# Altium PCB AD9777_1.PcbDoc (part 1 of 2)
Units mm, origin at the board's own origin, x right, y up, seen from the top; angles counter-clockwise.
Board outline 148.59 x 134.62 mm, 4 copper layers (Top Layer, Ground, POwer, Bottom Layer), stack 0.778 mm thick; 277 components, 168 nets, 827 pads, 113 vias.
Unrouted connection lines stored in the file: 4.
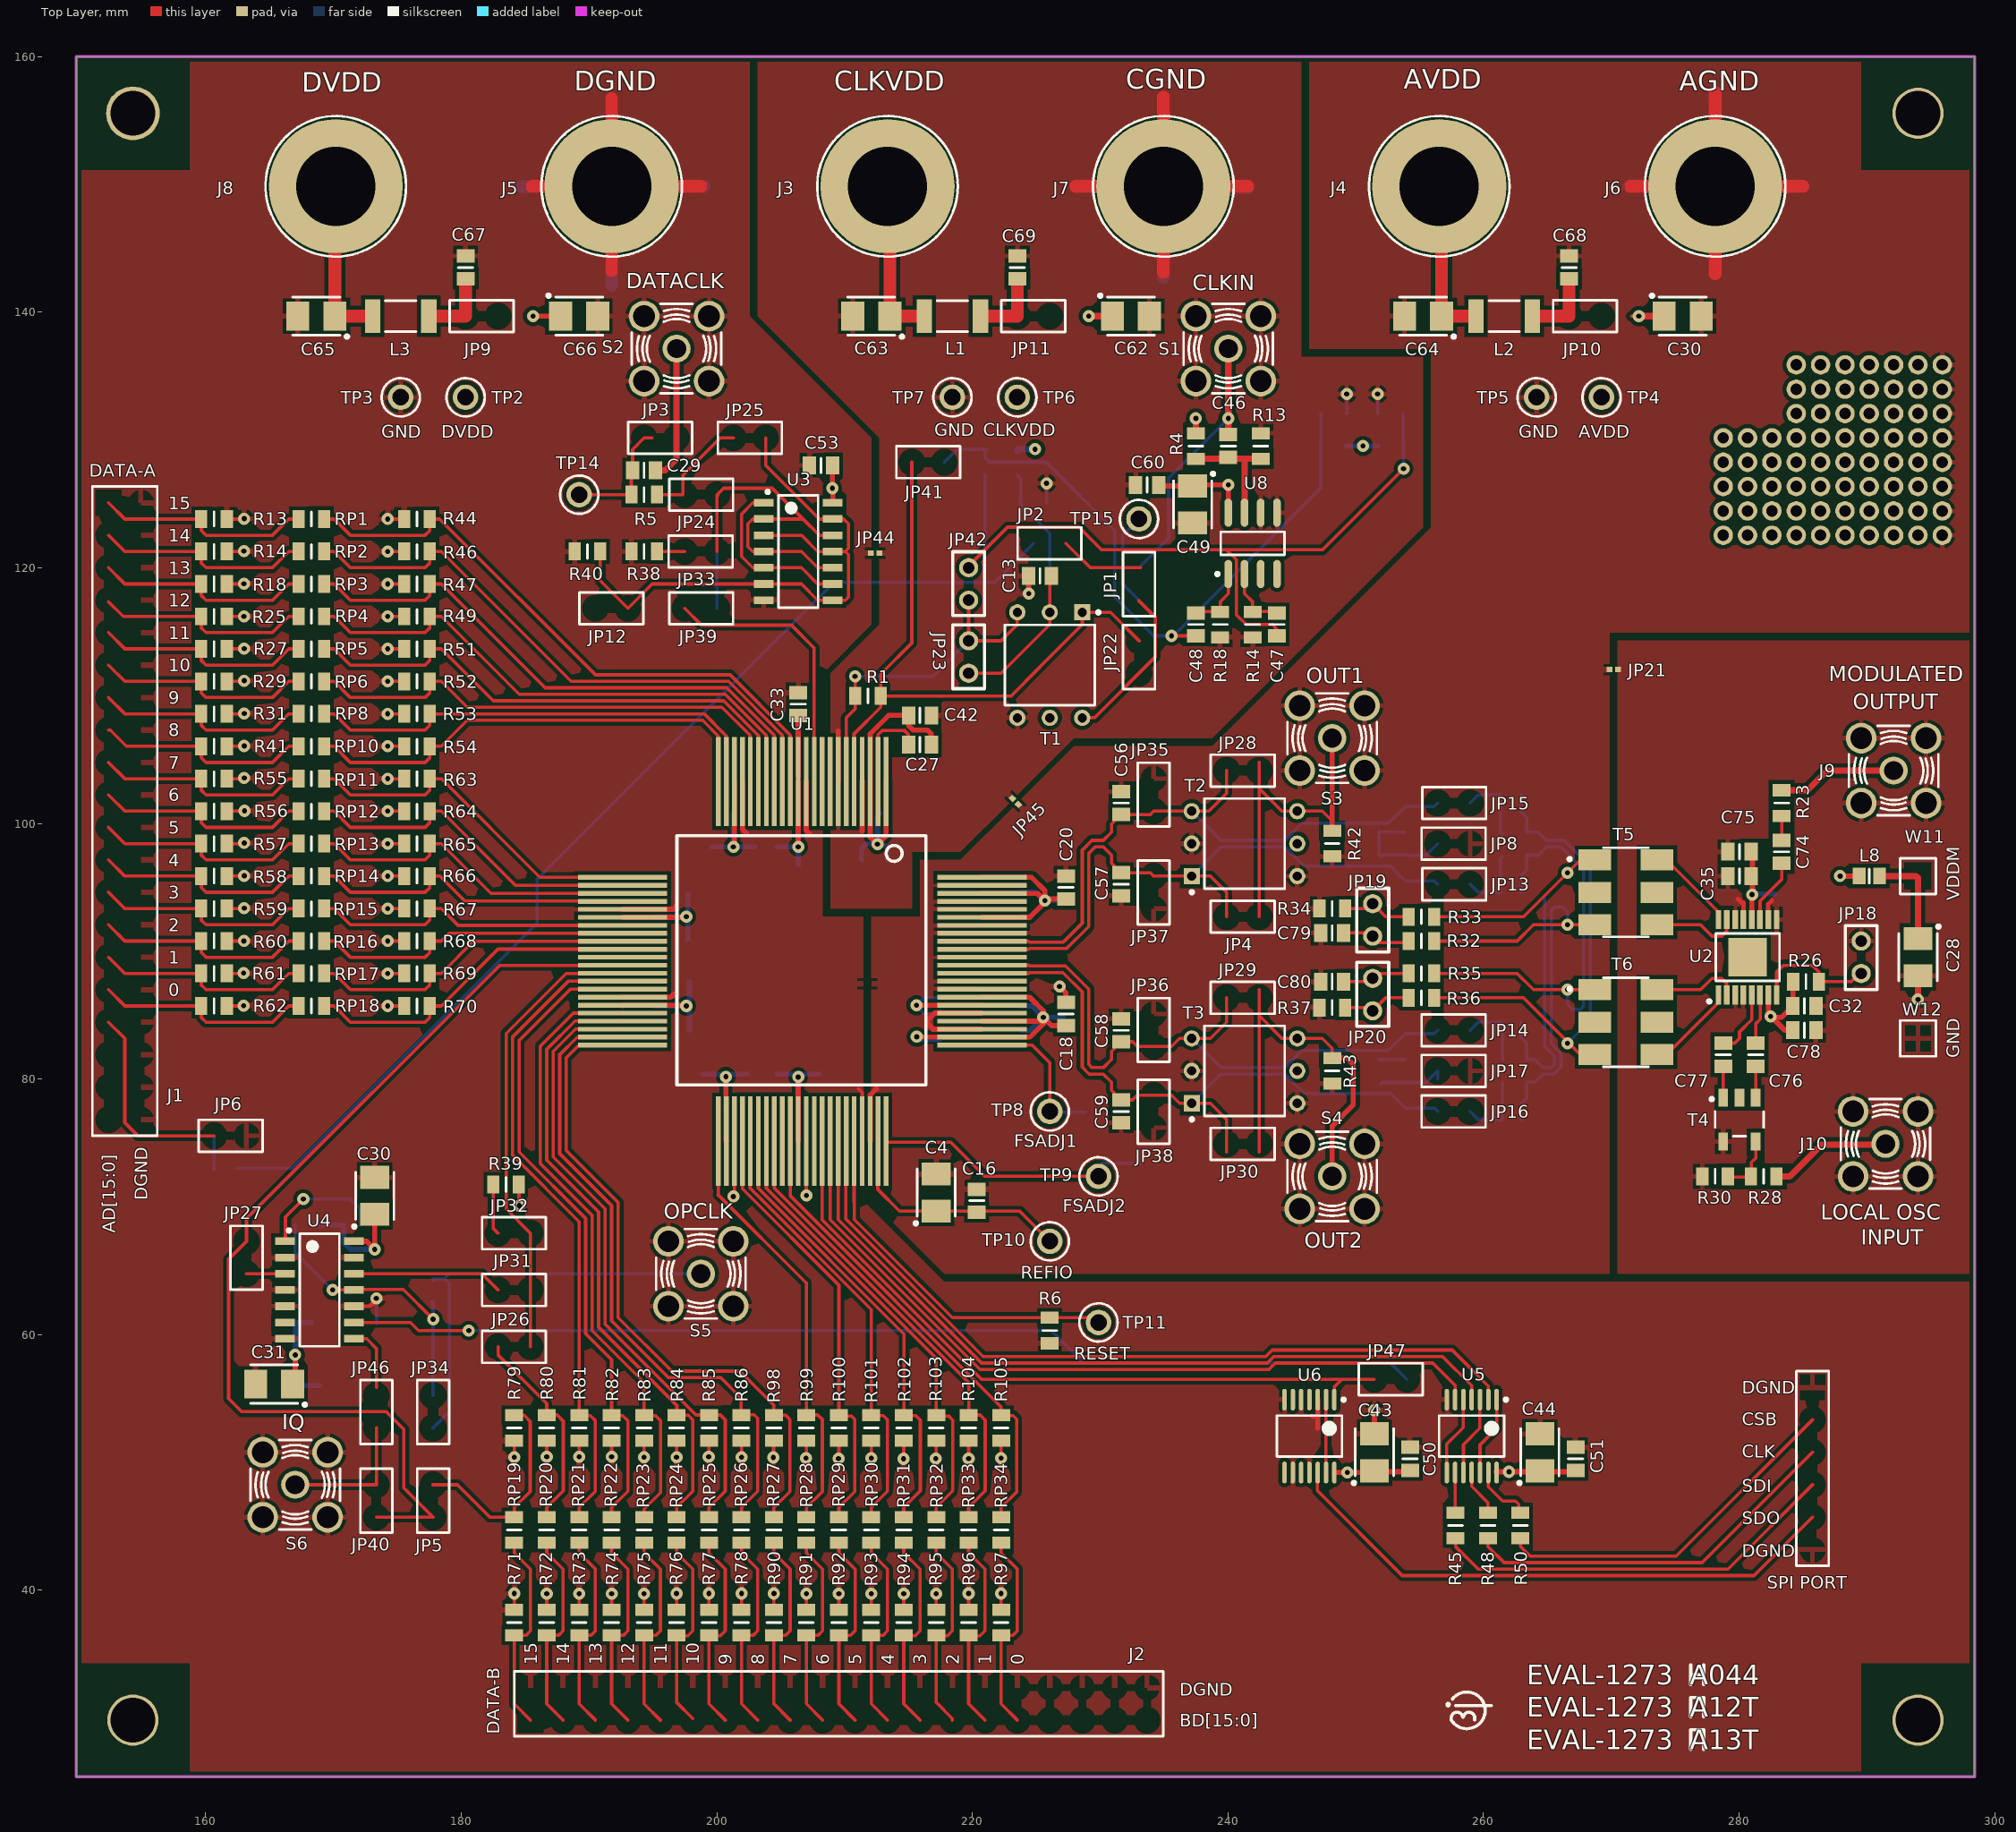
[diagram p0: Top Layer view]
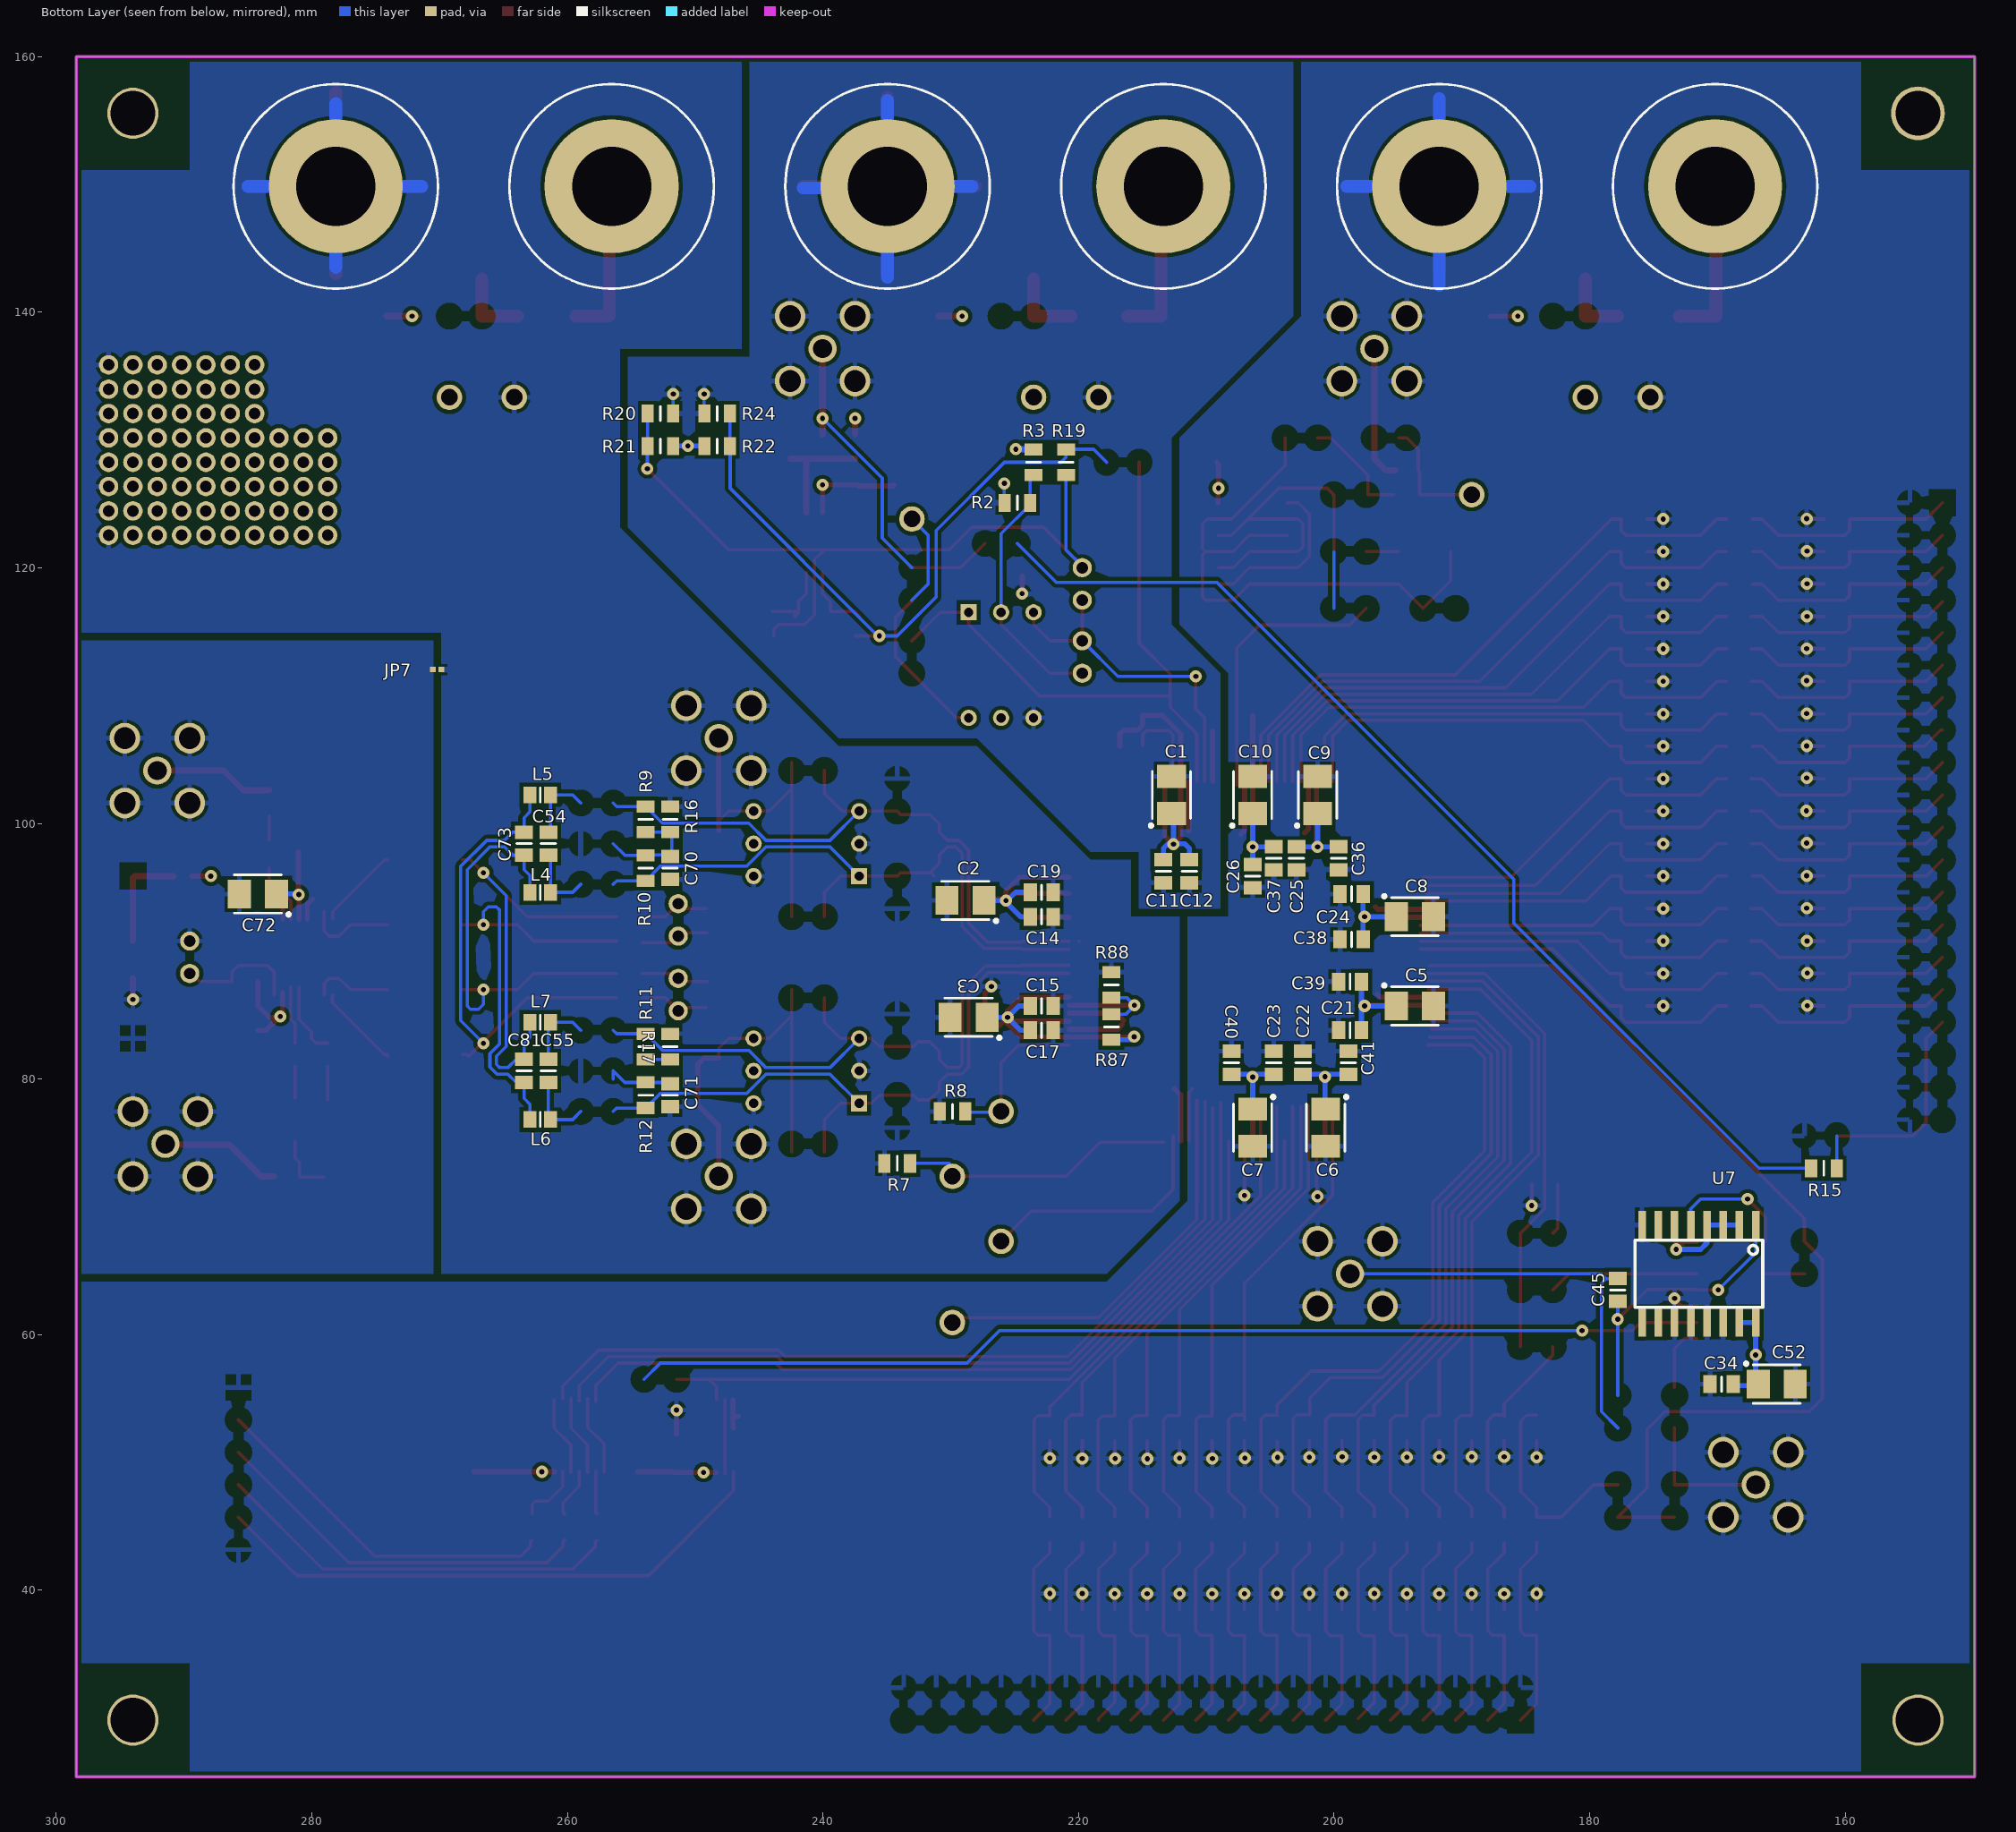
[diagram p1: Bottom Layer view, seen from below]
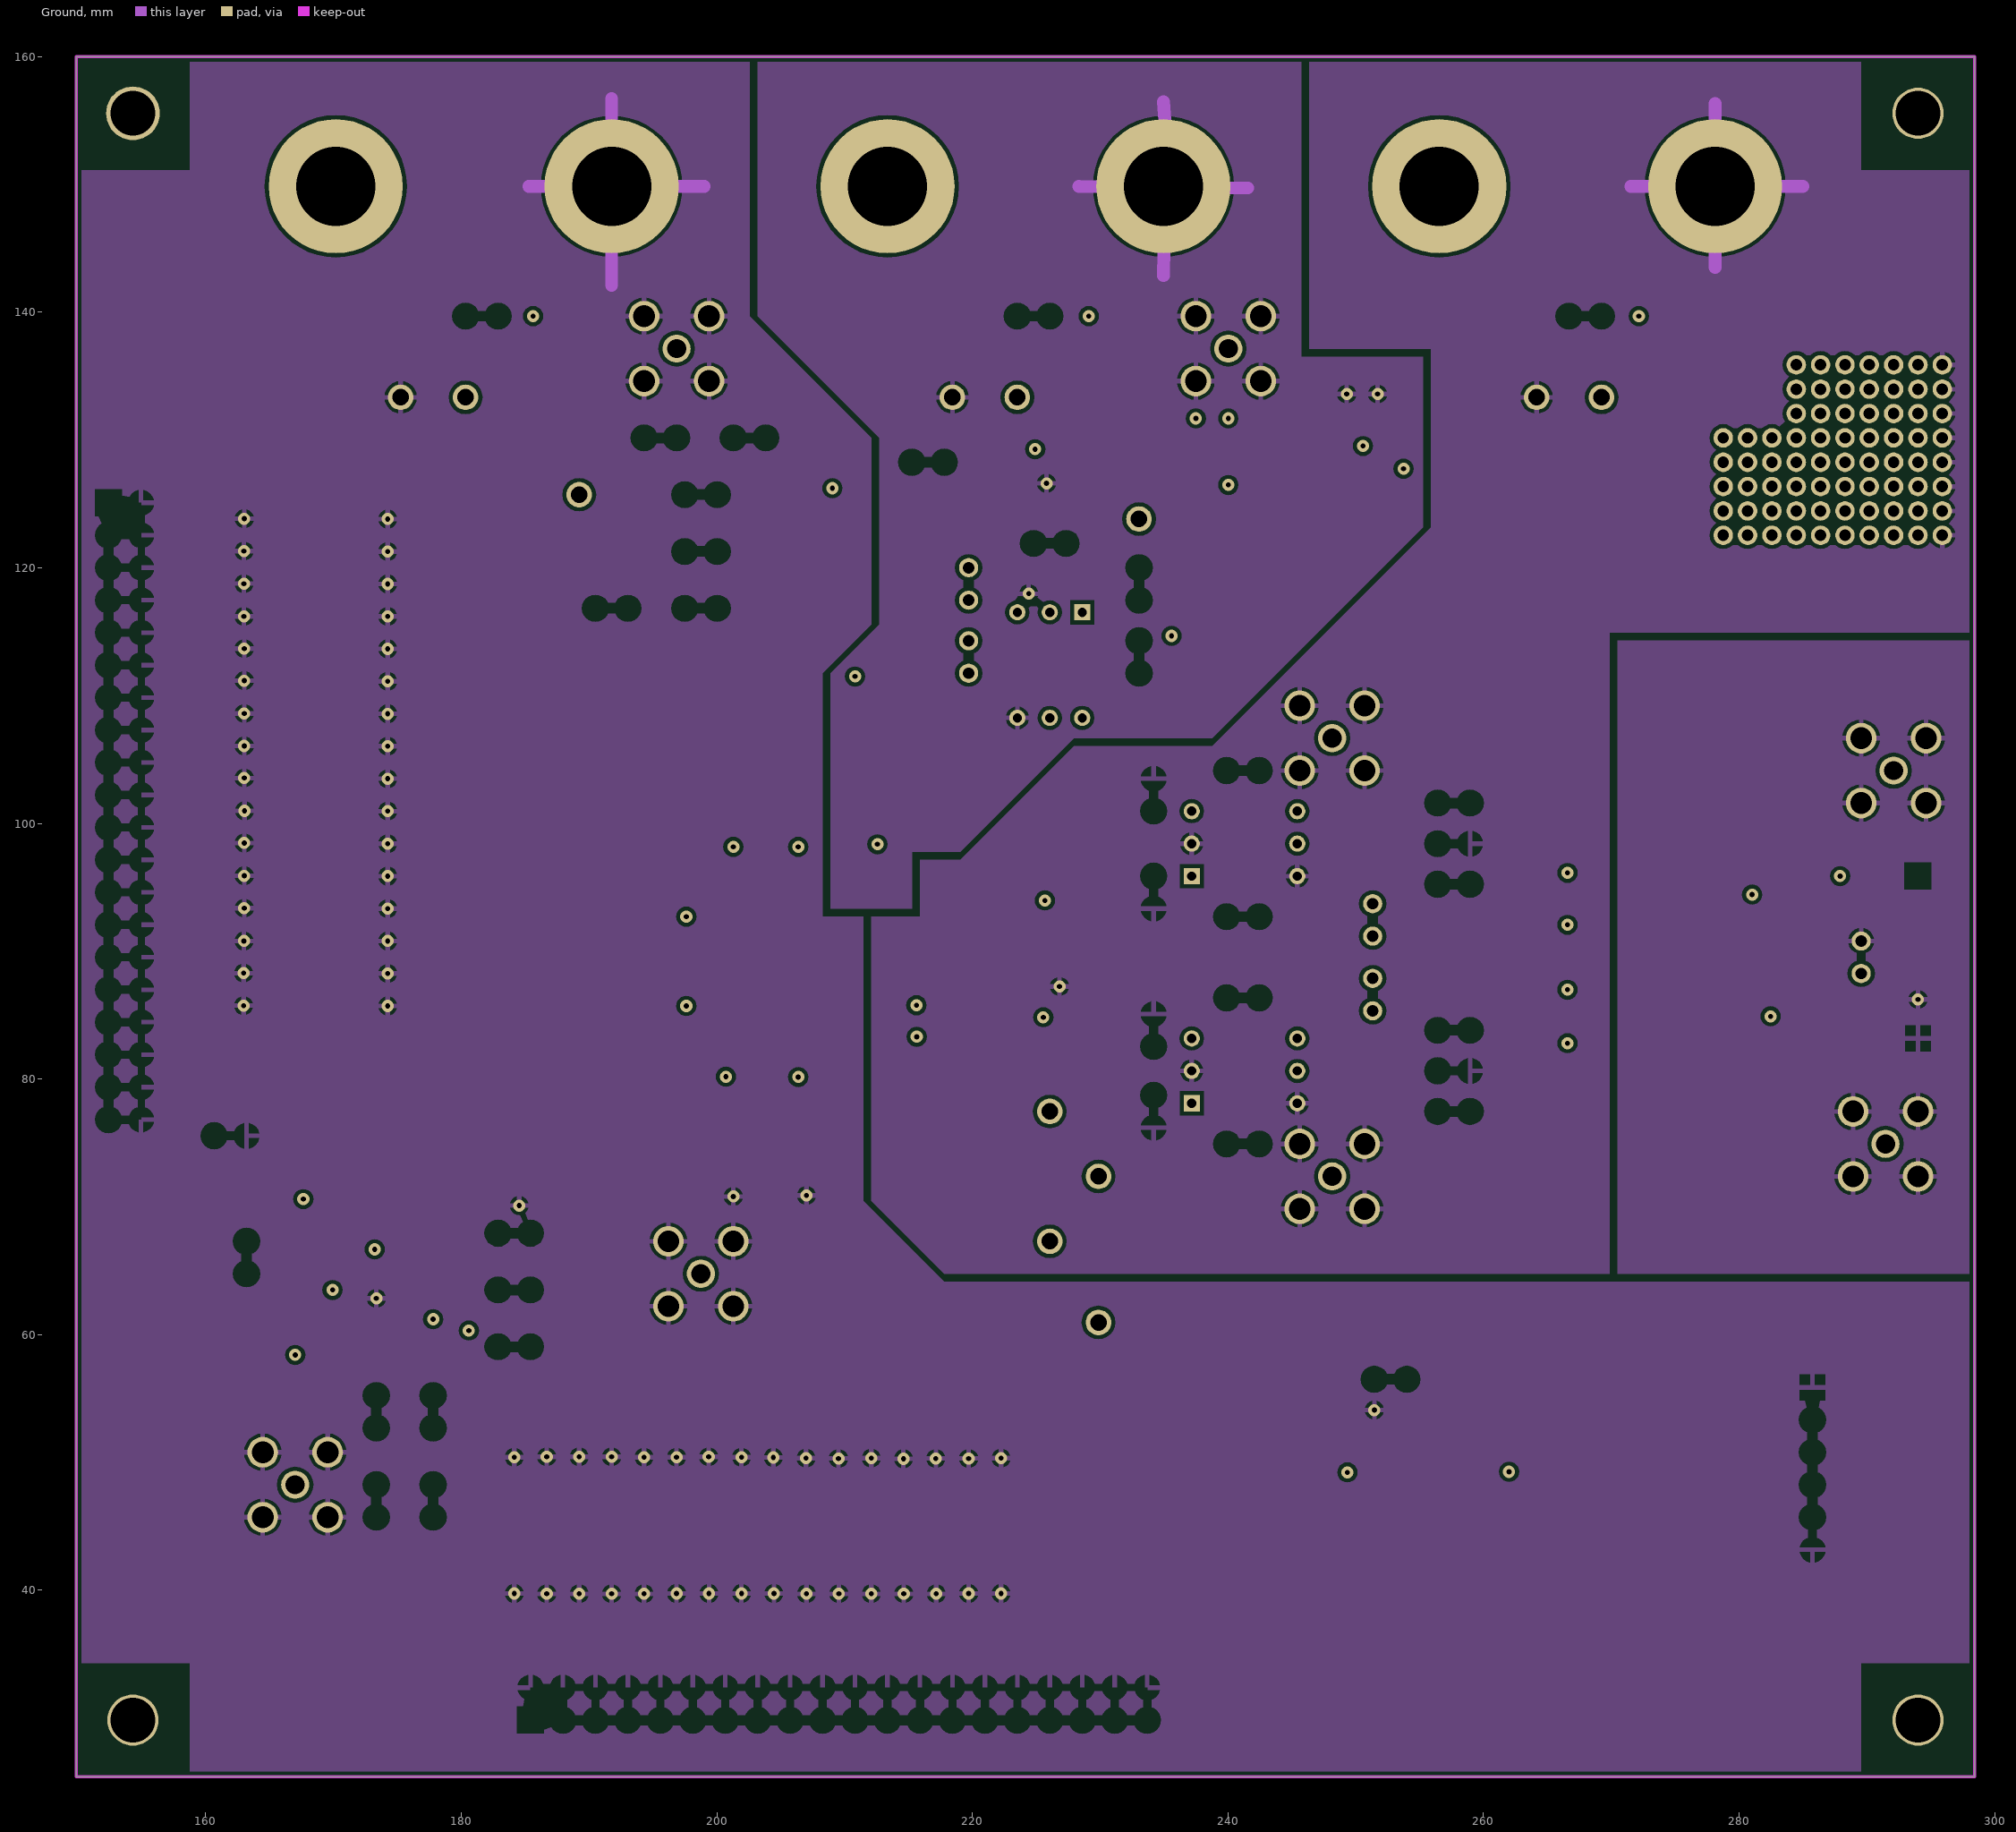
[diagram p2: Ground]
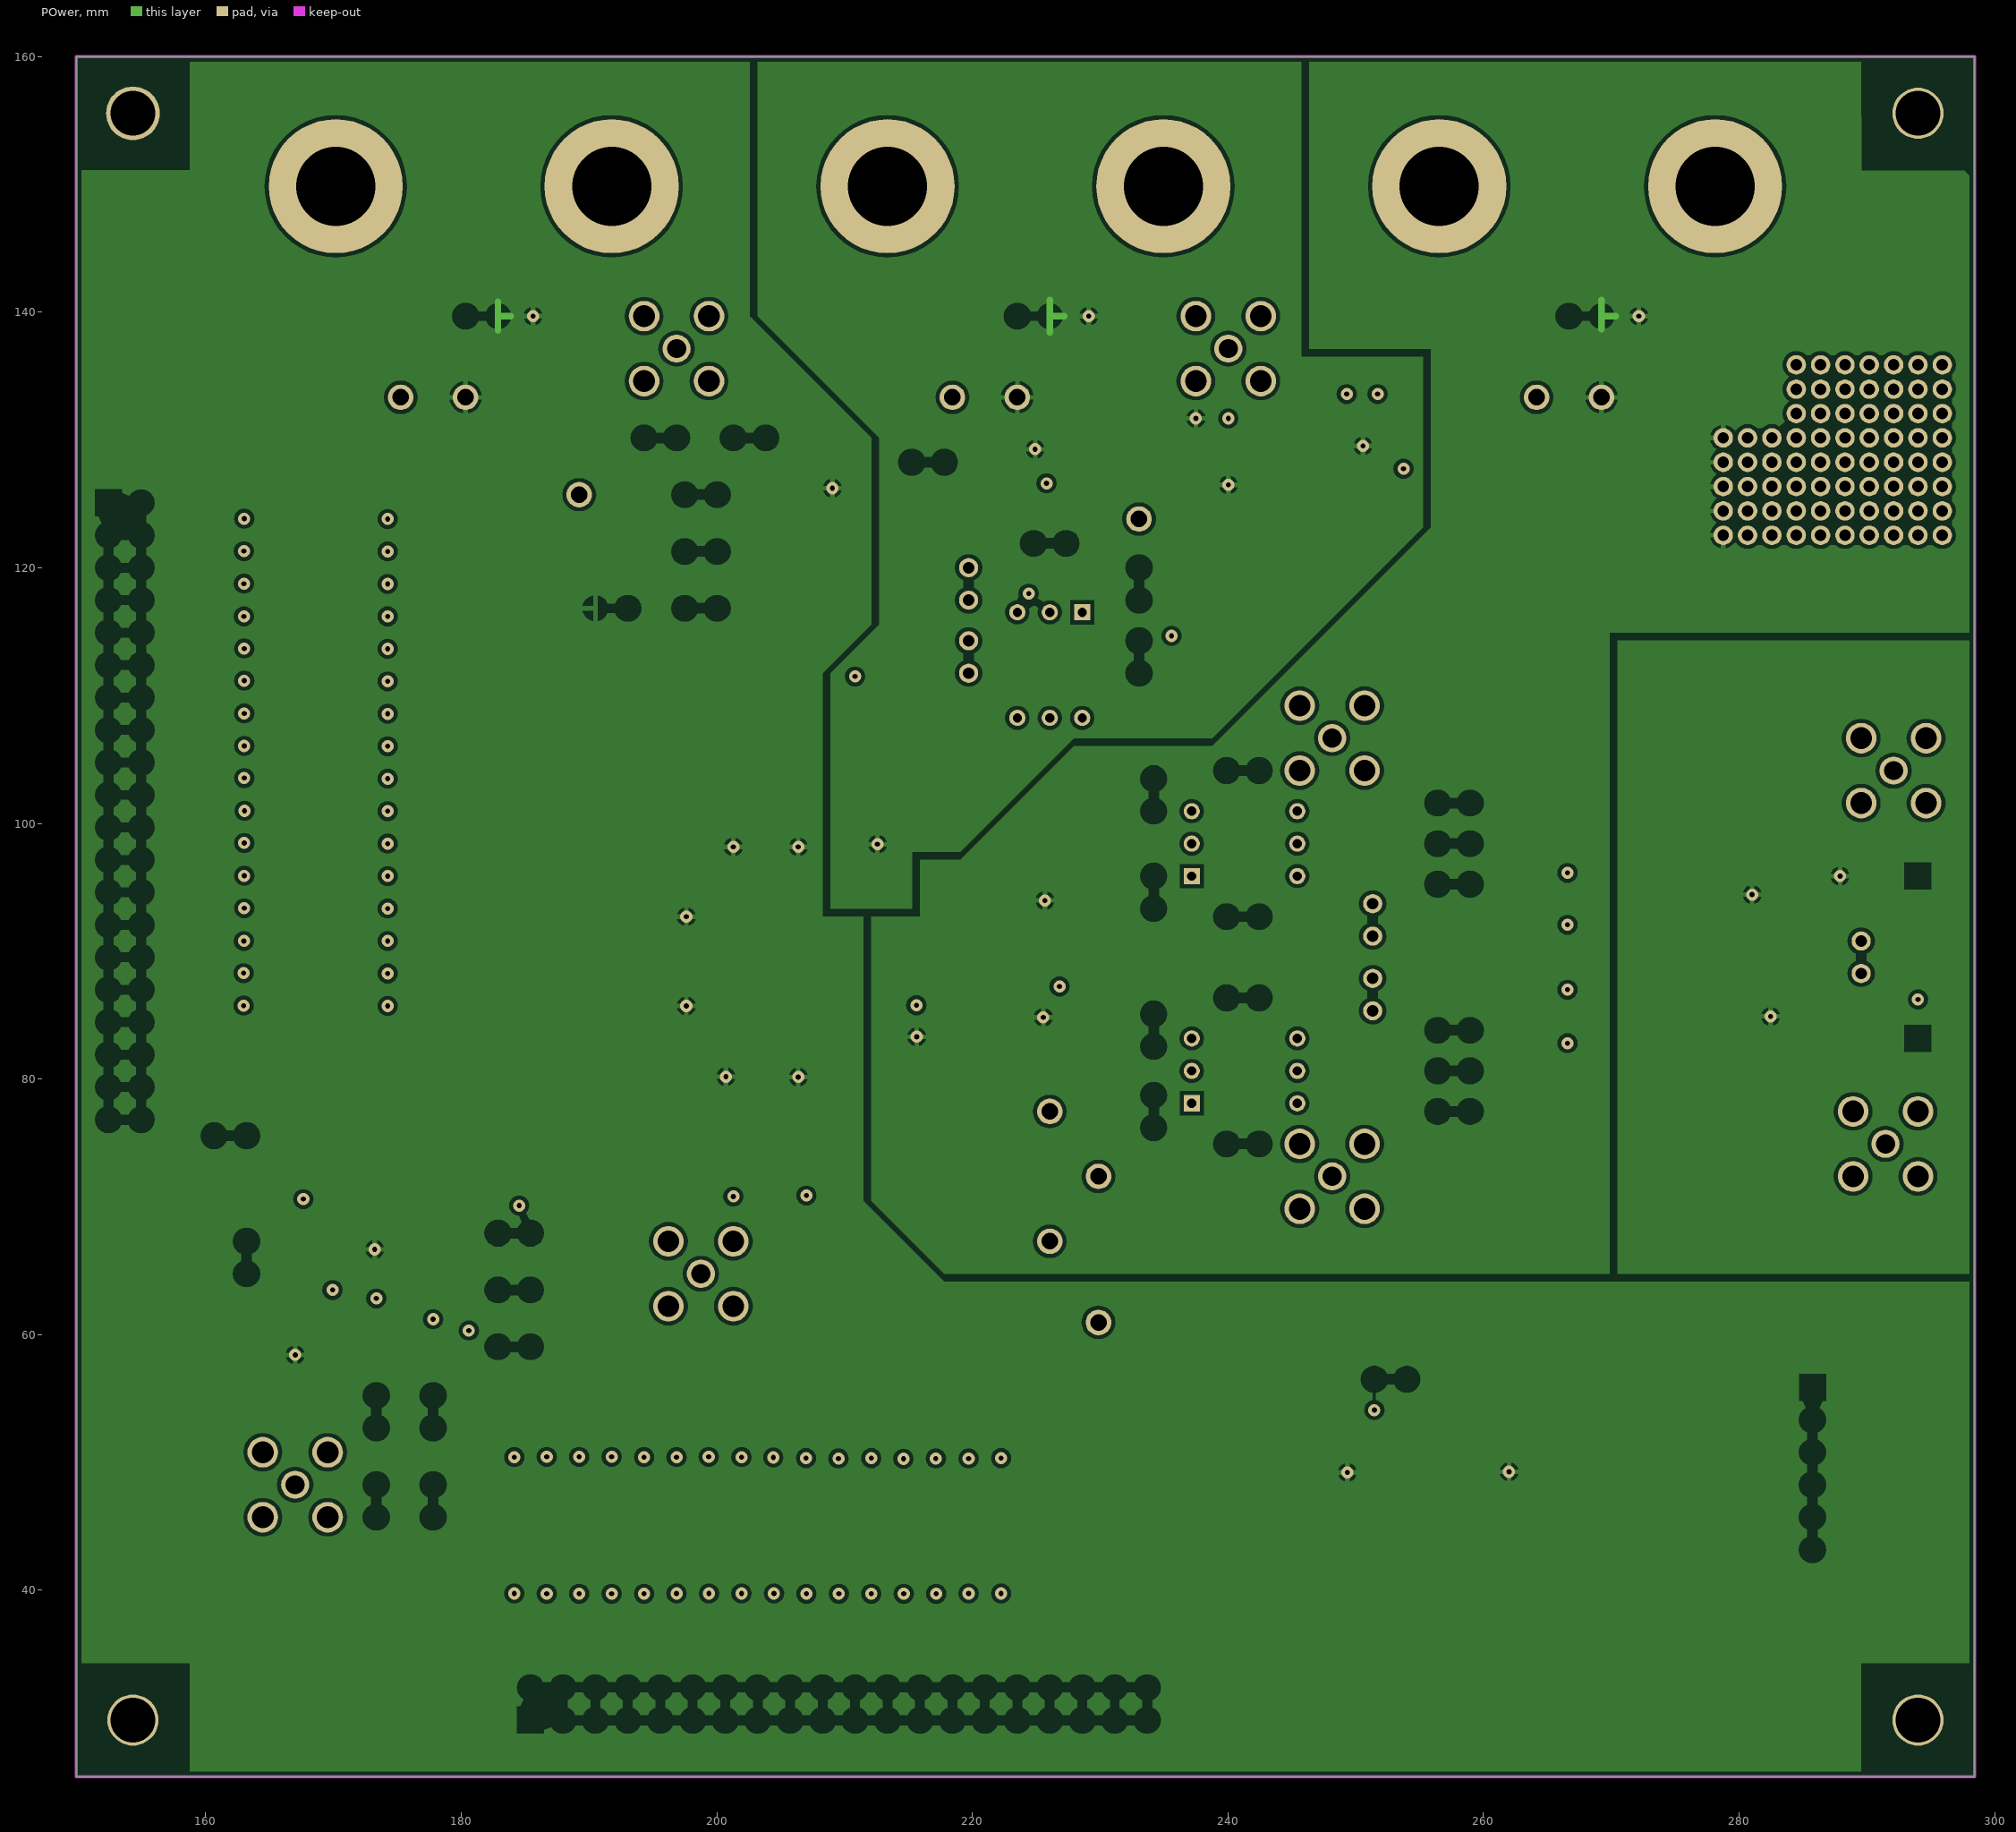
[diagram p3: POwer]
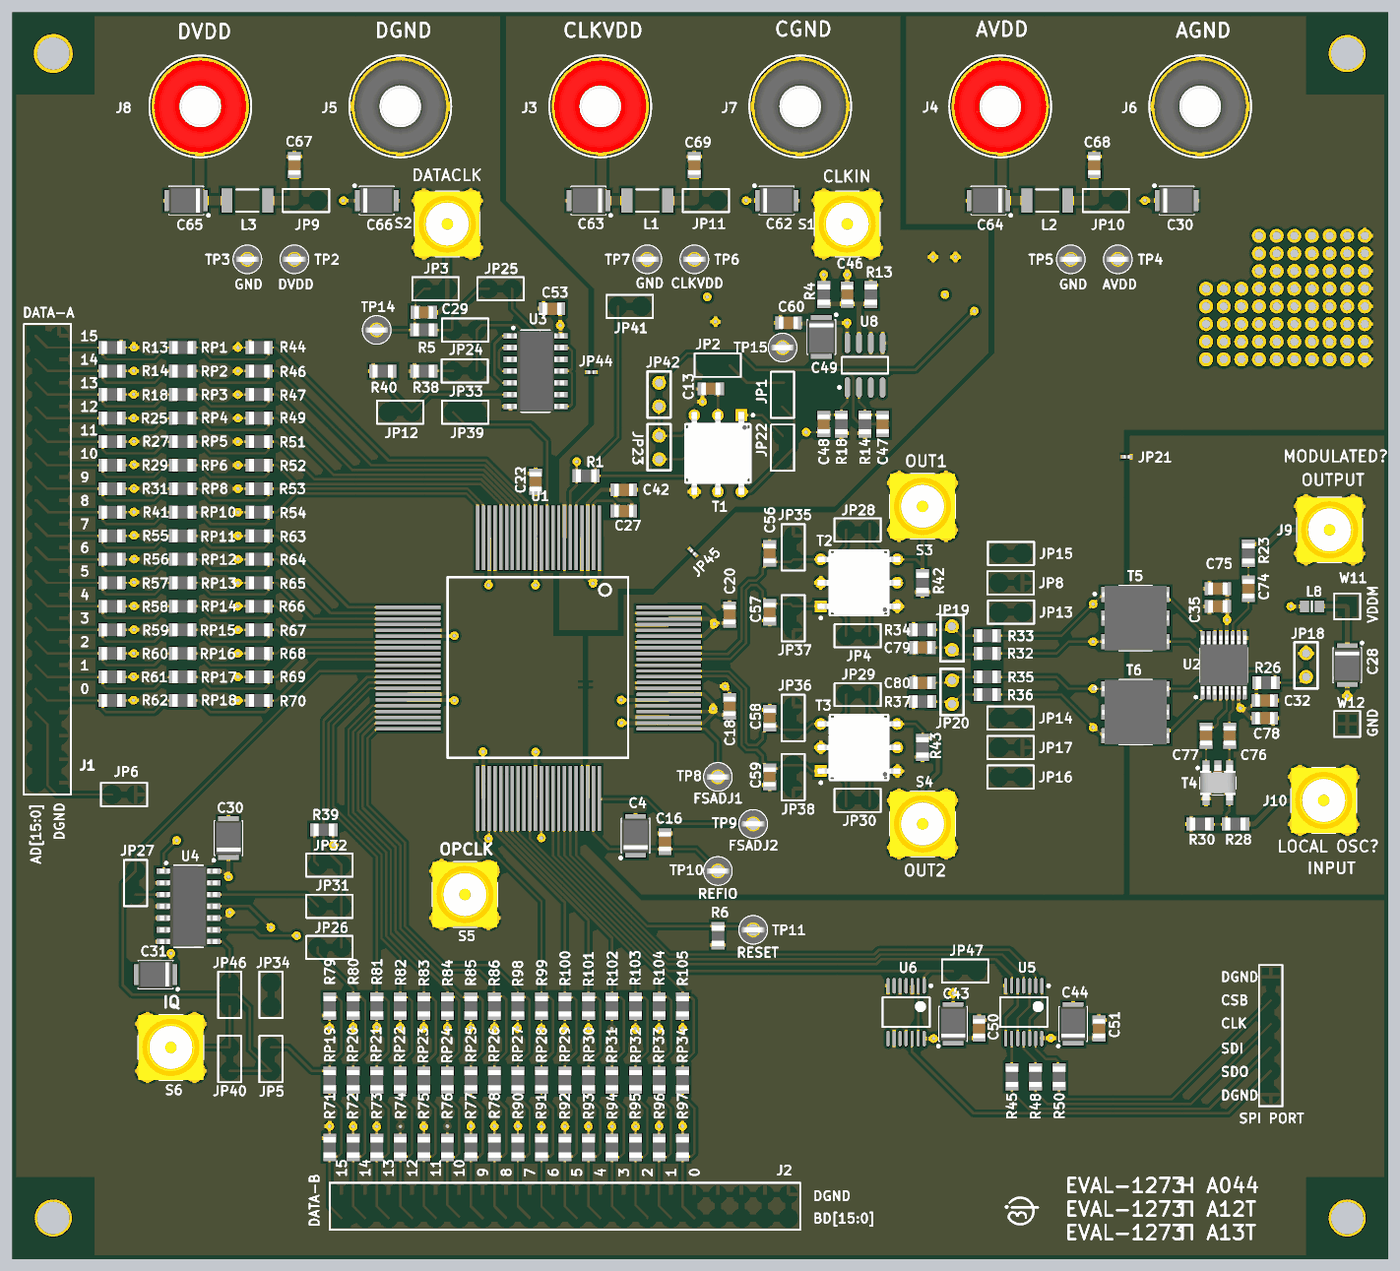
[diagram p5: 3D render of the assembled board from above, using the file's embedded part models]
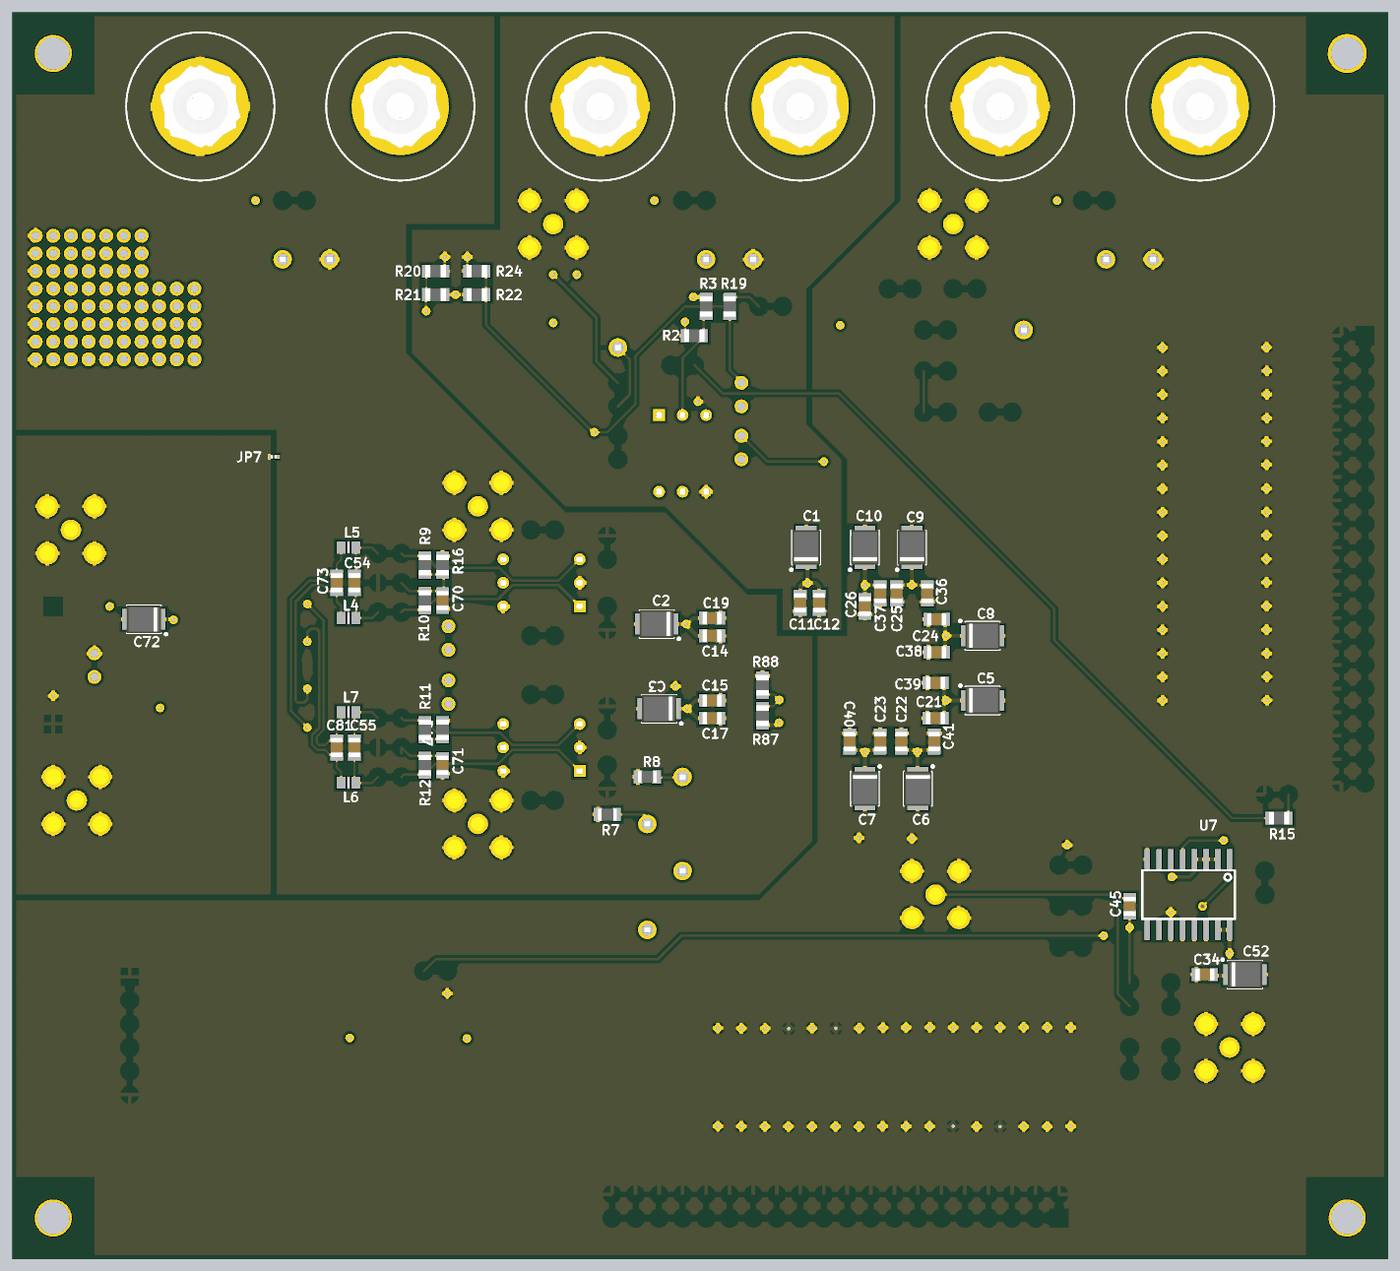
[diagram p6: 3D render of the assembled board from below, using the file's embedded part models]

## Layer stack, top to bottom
Top Solder: solder mask 0.0102, Solder Resist, Dk 3.5
Top Layer: signal copper 0.0356
Dielectric1: core 0.254, FR-4, Dk 4.2
Ground: signal copper 0.036
Dielectric2: prepreg 0.127, Dk 4.2
POwer: signal copper 0.036
Dielectric3: core 0.254, Dk 4.2
Bottom Layer: signal copper 0.0356
Bottom Solder: solder mask 0.0102, Solder Resist, Dk 3.5

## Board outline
149.86,160.02 298.45,160.02 298.45,25.4 149.86,25.4

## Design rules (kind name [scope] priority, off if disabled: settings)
Clearance Clearance_1 [All vs InPolygon] p1: gap=0.3 ignorepadtopadclearanceinfootprint=FALSE except(0: Arc-Hole Track-Hole SMDPad-Hole THPad-Hole Via-Hole Fill-Hole Poly-Hole Region-Hole Text-Hole) // Polygon
Clearance [All] p2: gap=0.1 ignorepadtopadclearanceinfootprint=FALSE except(0: Arc-Hole Track-Hole SMDPad-Hole THPad-Hole Via-Hole Fill-Hole Poly-Hole Region-Hole Text-Hole)
DiffPairsRouting DiffPairsRouting_1 [All] p1: maxlimit=0.254 minlimit=0.2 mostfreqgap=0.254 toplayer_minwidth=0.381 toplayer_maxwidth=0.381 toplayer_prefwidth=0.381 midlayer1_minwidth=0.381 midlayer1_maxwidth=0.381 midlayer1_prefwidth=0.381 midlayer2_minwidth=0.381 midlayer2_maxwidth=0.381 midlayer2_prefwidth=0.381 bottomlayer_minwidth=0.381 bottomlayer_maxwidth=0.381 bottomlayer_prefwidth=0.381 maxuncoupledlength=20
DiffPairsRouting [All] p2: maxlimit=0.254 minlimit=0.1 mostfreqgap=0.254 toplayer_minwidth=0.381 toplayer_maxwidth=0.381 toplayer_prefwidth=0.381 midlayer1_minwidth=0.381 midlayer1_maxwidth=0.381 midlayer1_prefwidth=0.381 midlayer2_minwidth=0.381 midlayer2_maxwidth=0.381 midlayer2_prefwidth=0.381 bottomlayer_minwidth=0.381 bottomlayer_maxwidth=0.381 bottomlayer_prefwidth=0.381 maxuncoupledlength=20
MatchedLengths [All] p1: tolerance=2.4 checknetsindiffpair=TRUE checkdiffpairvsdiffpair=FALSE checkxsignals=FALSE checkothers=FALSE
ParallelSegment [All] p1: limit=254 gap=0.254
PolygonConnect [All] p1: connectstyle=Relief reliefconductorwidth=0.4 reliefentries=4 polygonreliefangle="90 Angle" airgapwidth=0.254
RoutingVias [All] p1: holewidth=0.711 width=1.27 viastyle="Through Hole" minholewidth=0.711 minwidth=1.27 maxholewidth=0.711 maxwidth=1.27
SolderMaskExpansion [All] p1: expansion=0.102
Width Width_1 [All] p1: maxlimit=1 minlimit=0.1 preferedwidth=0.254
Width [All] p2: maxlimit=1 minlimit=0.1 preferedwidth=0.254
29 further rules are at their usual default settings.

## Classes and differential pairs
component class AD9777_L1: C28 C30 C32 C35 C54 C55 C62 C63 C64 C65 C66 C67 C68 C69 C72 C73 C74 C75 C76 C77 C78 C79 C80 C81 J3 J4 J5 J6 J7 J8 J9 J10 JP7 JP18 JP19 JP20 JP21 JP44 JP45 L1 L2 L3 L4 L5 L6 L7 L8 R23 R26 R28 R30 R32 R33 R34 R35 R36 R37 T4 T5 T6 TP2 TP3 TP4 TP5 TP6 TP7 U2 W11 W12
component class AD9777_L2: C1 C2 C3 C4 C5 C6 C7 C8 C9 C10 C11 C12 C13 C14 C15 C16 C17 C18 C19 C20 C21 C22 C23 C24 C25 C26 C27 C29 C36 C37 C38 C39 C40 C41 C42 C45 C56 C57 C58 C59 C70 C71 JP23 R1 R2 R3 R5 R6 R7 R8 R9 R10 R11 R12 R16 R17 R38 R39 R40 R42 R43 R87 R88 S1 S2 S3 S4 S5 S6 T1 T2 T3 TP8 TP9 TP10 TP11 TP14 TP15 TR3 U1
component class AD9777_L3: C30 C31 C33 C34 C52 C53 R13 R14 R15 R18 R25 R27 R29 R31 R41 R44 R46 R47 R49 R51 R52 R53 R54 R55 R56 R57 R58 R59 R60 R61 R62 R63 R64 R65 R66 R67 R68 R69 R70 RP1 RP2 RP3 RP4 RP5 RP6 RP8 RP10 RP11 RP12 RP13 RP14 RP15 RP16 RP17 RP18 U3 U4 U7
component class AD9777_L4: C43 C44 C46 C47 C48 C49 C50 C51 C60 JP42 R4 R13 R14 R18 R19 R20 R21 R22 R24 R45 R48 R50 R71 R72 R73 R74 R75 R76 R77 R78 R79 R80 R81 R82 R83 R84 R85 R86 R90 R91 R92 R93 R94 R95 R96 R97 R98 R99 R100 R101 R102 R103 R104 R105 RP19 RP20 RP21 RP22 RP23 RP24 RP25 RP26 RP27 RP28 RP29 RP30 RP31 RP32 RP33 RP34 U5 U6 U8
differential pair O1: +O1_P -O1_N
differential pair O2: +O2_P -O2_N
differential pair IOUTA1: +IOUTA1_P -IOUTA1_N
differential pair IOUTA2: +IOUTA2_P -IOUTA2_N
differential pair IBB: +IBB_P -IBB_N
differential pair LOI: +LOI_P -LOI_N
differential pair QBB: +QBB_P -QBB_N

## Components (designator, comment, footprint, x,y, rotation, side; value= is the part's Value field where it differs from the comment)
C1 "10uF" CAPMP3528X210N 212.725,102.235 r90 bottom
C2 "10uF" CAPMP3528X210N 228.854,93.98 r0 bottom
C3 "10uF" CAPMP3528X210N 228.6,84.836 r0 bottom
C4 "10uF" CAPMP3528X210N 217.17,71.12 r90 top
C5 "10uF" CAPMP3528X210N 193.675,85.725 r180 bottom
C6 "10uF" CAPMP3528X210N 200.66,76.2 r270 bottom
C7 "10uF" CAPMP3528X210N 206.375,76.2 r270 bottom
C8 "10uF" CAPMP3528X210N 193.675,92.71 r180 bottom
C9 "10uF" CAPMP3528X210N 201.295,102.235 r90 bottom
C10 "10uF" CAPMP3528X210N 206.375,102.235 r90 bottom
C11 "0.1uF" CAPC2012X135N 213.36,96.266 r270 bottom
C12 "0.1uF" CAPC2012X135N 211.328,96.266 r270 bottom
C13 "0.1uF" CAPC2012X135N 225.298,119.38 r0 top
C14 "0.1uF" CAPC2012X135N 222.885,92.71 r180 bottom
C15 "0.1uF" CAPC2012X135N 222.885,85.725 r180 bottom
C16 "0.1uF" CAPC2012X135N 220.345,70.485 r90 top
C17 "0.1uF" CAPC2012X135N 222.885,83.82 r180 bottom
C18 "0.1uF" CAPC2012X135N 227.33,85.09 r90 top
C19 "0.1uF" CAPC2012X135N 222.885,94.615 r180 bottom
C20 "0.1uF" CAPC2012X135N 227.33,94.996 r90 top
C21 "1nF" CAPC2012X135N 198.755,83.82 r0 bottom
C22 "1nF" CAPC2012X135N 202.438,81.28 r90 bottom
C23 "1nF" CAPC2012X135N 204.724,81.28 r90 bottom
C24 "1nF" CAPC2012X135N 198.628,94.488 r0 bottom
C25 "1nF" CAPC2012X135N 202.946,97.282 r270 bottom
C26 "1nF" CAPC2012X135N 206.375,95.885 r270 bottom
C27 "1pF" CAPC2012X135N 215.9,106.172 r180 top
C28 "22uF" CAPMP3528X210N 294.005,89.535 r270 top
C29 "0.1uF" CAPC2012X135N 194.31,127.635 r0 top
C30 "4.7uF" CAPMP3528X210N 173.228,70.866 r90 top
C30 "22uF" CAPMP3528X210N 275.59,139.7 r0 top
C31 "4.7uF" CAPMP3528X210N 165.354,56.134 r180 top
C32 "0.1uF" CAPC2012X135N 285.115,85.725 r0 top
C33 "0.1uF" CAPC2012X135N 206.375,109.347 r90 top
C34 "0.1uF" CAPC2012X135N 169.672,56.134 r0 bottom
C35 "100pF" CAPC2012X135N 280.035,95.885 r180 top
C36 "0.01uF" CAPC2012X135N 199.644,97.282 r270 bottom
C37 "0.01uF" CAPC2012X135N 204.724,97.282 r270 bottom
C38 "0.01uF" CAPC2012X135N 198.628,90.932 r0 bottom
C39 "0.01uF" CAPC2012X135N 198.755,87.63 r0 bottom
C40 "0.01uF" CAPC2012X135N 208.026,81.28 r90 bottom
C41 "0.01uF" CAPC2012X135N 198.882,81.28 r90 bottom
C42 "0.1uF" CAPC2012X135N 215.9,108.458 r0 top
C43 "4.7uF" CAPMP3528X210N 251.46,50.8 r90 top
C44 "4.7uF" CAPMP3528X210N 264.414,50.8 r90 top
C45 "0.01uF" CAPC2012X135N 177.8,63.5 r270 bottom
C46 "0.1uF" CAPC2012X135N 240.03,129.54 r270 top
C47 "1nF" CAPC2012X135N 243.84,115.57 r270 top
C48 "1nF" CAPC2012X135N 237.49,115.57 r270 top
C49 "4.7uF" CAPMP3528X210N 237.236,124.968 r270 top
C50 "0.1uF" CAPC2012X135N 254.254,50.292 r270 top
C51 "0.1uF" CAPC2012X135N 267.208,50.292 r270 top
C52 "4.7uF" CAPMP3528X210N 165.354,56.134 r180 bottom
C53 "0.1uF" CAPC2012X135N 208.153,128.016 r180 top
C54 "DNP" CAPC2012X135N 261.493,98.425 r270 bottom
C55 "DNP" CAPC2012X135N 261.493,80.645 r270 bottom
C56 "DNP" CAPC2012X135N 231.648,101.6 r270 top
C57 "DNP" CAPC2012X135N 231.648,95.25 r90 top
C58 "DNP" CAPC2012X135N 231.648,83.82 r270 top
C59 "DNP" CAPC2012X135N 231.648,77.47 r90 top
C60 "0.1uF" CAPC2012X135N 233.68,126.492 r0 top
C62 "22uF" CAPMP3528X210N 232.41,139.7 r0 top
C63 "22uF" CAPMP3528X210N 212.09,139.7 r180 top
C64 "22uF" CAPMP3528X210N 255.27,139.7 r180 top
C65 "22uF" CAPMP3528X210N 168.656,139.7 r180 top
C66 "22uF" CAPMP3528X210N 189.23,139.7 r0 top
C67 "0.1uF" CAPC2012X135N 180.34,143.51 r90 top
C68 "0.1uF" CAPC2012X135N 266.7,143.51 r90 top
C69 "0.1uF" CAPC2012X135N 223.52,143.51 r90 top
C70 "0.1uF" CAPC2012X135N 251.968,96.52 r270 bottom
C71 "0.1uF" CAPC2012X135N 251.968,78.74 r270 bottom
C72 "10uF" CAPMP3528X210N 284.226,94.488 r0 bottom
C73 "DNP" CAPC2012X135N 263.398,98.425 r270 bottom
C74 "100pF" CAPC2012X135N 283.337,97.79 r90 top
C75 "0.1uF" CAPC2012X135N 280.035,97.79 r180 top
C76 "100pF" CAPC2012X135N 281.305,81.915 r90 top
C77 "100pF" CAPC2012X135N 278.765,81.915 r90 top
C78 "0.1uF" CAPC2012X135N 285.115,83.82 r0 top
C79 "DNP" CAPC2012X135N 248.158,91.44 r180 top
C80 "DNP" CAPC2012X135N 248.158,87.63 r0 top
C81 "DNP" CAPC2012X135N 263.398,80.645 r270 bottom
J3 "Banana" "SKS-HIRSCHMANN_930 176-101" 213.36,149.86 r0 top
J4 "Banana" "SKS-HIRSCHMANN_930 176-101" 256.54,149.86 r0 top
J5 "Banana" "SKS-HIRSCHMANN_930 176-100" 191.77,149.86 r0 top
J6 "Banana" "SKS-HIRSCHMANN_930 176-100" 278.13,149.86 r0 top
J7 "Banana" "SKS-HIRSCHMANN_930 176-100" 234.95,149.86 r0 top
J8 "Banana" "SKS-HIRSCHMANN_930 176-101" 170.18,149.86 r0 top
J9 "MODULATED OUTPUT" AMPHENOL_132134 292.1,104.14 r180 top
J10 "LOCAL OSC INPUT" AMPHENOL_132134 291.465,74.93 r180 top
JP7 "0" RESC0603X28N 270.205,112.039 r0 bottom
JP18 "Jumper" PLS2 289.56,88.265 r0 top
JP19 "Jumper" PLS2 251.333,91.186 r0 top
JP20 "Jumper" PLS2 251.333,87.884 r180 top
JP21 "0" RESC0603X28N 270.205,112.039 r0 top
JP23 "Jumper" PLS2 219.71,114.3 r180 top
JP42 "Jumper" PLS2 219.71,120.015 r180 top
JP44 "0" RESC0603X28N 212.395,121.158 r0 top
JP45 "0" RESC0603X28N 223.368,101.727 r135 top
L1 "FERRITE" 12Z-2010 218.44,139.7 r180 top
L2 "FERRITE" 12Z-2010 261.62,139.7 r180 top
L3 "FERRITE" 12Z-2010 175.26,139.7 r180 top
L4 "DNP" 6-0805_L 262.128,94.615 r180 bottom
L5 "DNP" 6-0805_L 262.128,102.235 r180 bottom
L6 "DNP" 6-0805_L 262.128,76.835 r180 bottom
L7 "DNP" 6-0805_L 262.128,84.455 r180 bottom
L8 "FERRITE" 6-0805_L 290.195,95.885 r0 top
R1 "200K" RESC2012X60N 211.836,109.982 r0 top
R2 "1K" RESC2012X60N 224.79,125.095 r180 bottom
R3 "1K" RESC2012X60N 223.52,128.27 r90 bottom
R4 "120R" RESC2012X60N 237.49,129.54 r90 top
R5 "49.9R" RESC2012X60N 194.31,125.73 r180 top
R6 "1K" RESC2012X60N 226.06,60.325 r90 top
R7 "2K" RESC2013X64N 234.188,73.406 r180 bottom
R8 "1K" RESC2013X64N 229.87,77.47 r180 bottom
R9 "51k" RESC2012X60N 253.873,100.33 r90 bottom
R10 "51k" RESC2012X60N 253.873,96.52 r270 bottom
R11 "51K" RESC2012X60N 253.873,82.55 r90 bottom
R12 "51K" RESC2012X60N 253.873,78.74 r270 bottom
R13 "120" RESC2012X60N 242.57,129.54 r270 top
R13 "50K" RESC2012X60N 160.655,123.825 r180 top
R14 "DNP" RESC2012X60N 241.935,115.57 r90 top
R14 "50K" RESC2012X60N 160.655,121.285 r180 top
R15 "220R" RESC2012X60N 161.671,73.025 r0 bottom
R16 "10k" RESC2012X60N 251.968,100.33 r270 bottom
R17 "10K" RESC2012X60N 251.968,82.55 r270 bottom
R18 "DNP" RESC2012X60N 239.395,115.57 r90 top
R18 "50K" RESC2012X60N 160.655,118.745 r180 top
R19 "100R" RESC2012X60N 220.98,128.27 r270 bottom
R20 "DNP" RESC2012X60N 252.73,132.08 r180 bottom
R21 "DNP" RESC2012X60N 252.73,129.54 r180 bottom
R22 "DNP" RESC2012X60N 248.285,129.54 r0 bottom
R23 "0R" RESC2012X60N 283.337,101.6 r90 top
R24 "DNP" RESC2012X60N 248.285,132.08 r0 bottom
R25 "50K" RESC2012X60N 160.655,116.205 r180 top
R26 "1K" RESC2012X60N 285.242,87.63 r180 top
R27 "50K" RESC2012X60N 160.655,113.665 r180 top
R28 "0R" RESC2012X60N 281.94,72.39 r180 top
R29 "50K" RESC2012X60N 160.655,111.125 r180 top
R30 "DNP" RESC2012X60N 278.13,72.39 r0 top
R31 "50K" RESC2012X60N 160.655,108.585 r180 top
R32 "51R" RESC2012X60N 255.143,90.805 r180 top
R33 "51R" RESC2012X60N 255.143,92.71 r180 top
R34 "DNP" RESC2012X60N 248.158,93.345 r180 top
R35 "51R" RESC2012X60N 255.143,88.265 r180 top
R36 "51R" RESC2012X60N 255.143,86.36 r180 top
R37 "DNP" RESC2012X60N 248.158,85.598 r180 top
R38 "10K" RESC2012X60N 194.31,121.285 r0 top
R39 "1K" RESC2012X60N 183.515,71.755 r0 top
R40 "5K" RESC2012X60N 189.865,121.285 r0 top
R41 "50K" RESC2012X60N 160.655,106.045 r180 top
R42 "49.9K" RESC2012X60N 248.158,98.425 r270 top
R43 "49.9k" RESC2012X60N 248.158,80.645 r270 top
R44 "50K" RESC2012X60N 176.53,123.825 r0 top
R45 "9K" RESC2012X60N 257.81,45.085 r270 top
R46 "50K" RESC2012X60N 176.53,121.285 r0 top
R47 "50K" RESC2012X60N 176.53,118.745 r0 top
R48 "9K" RESC2012X60N 260.35,45.085 r270 top
R49 "50K" RESC2012X60N 176.53,116.205 r0 top
R50 "9K" RESC2012X60N 262.89,45.085 r90 top
R51 "50K" RESC2012X60N 176.53,113.665 r0 top
R52 "50K" RESC2012X60N 176.53,111.125 r0 top
R53 "50K" RESC2012X60N 176.53,108.585 r0 top
R54 "50K" RESC2012X60N 176.53,106.045 r0 top
R55 "50K" RESC2012X60N 160.655,103.505 r0 top
R56 "50K" RESC2012X60N 160.655,100.965 r0 top
R57 "50K" RESC2012X60N 160.655,98.425 r0 top
R58 "50K" RESC2012X60N 160.655,95.885 r0 top
R59 "50K" RESC2012X60N 160.655,93.345 r0 top
R60 "50K" RESC2012X60N 160.655,90.805 r0 top
R61 "50K" RESC2012X60N 160.655,88.265 r0 top
R62 "50K" RESC2012X60N 160.655,85.725 r0 top
R63 "50K" RESC2012X60N 176.53,103.505 r180 top
R64 "50K" RESC2012X60N 176.53,100.965 r180 top
R65 "50K" RESC2012X60N 176.53,98.425 r180 top
R66 "50K" RESC2012X60N 176.53,95.885 r180 top
R67 "50K" RESC2012X60N 176.53,93.345 r180 top
R68 "50K" RESC2012X60N 176.53,90.805 r180 top
R69 "50K" RESC2012X60N 176.53,88.265 r180 top
R70 "50K" RESC2012X60N 176.53,85.725 r180 top
R71 "50K" RESC2012X60N 184.15,37.465 r270 top
R72 "50K" RESC2012X60N 186.69,37.465 r270 top
R73 "50K" RESC2012X60N 189.23,37.465 r270 top
R74 "50K" RESC2012X60N 191.77,37.465 r270 top
R75 "50K" RESC2012X60N 194.31,37.465 r270 top
R76 "50K" RESC2012X60N 196.85,37.465 r270 top
R77 "50K" RESC2012X60N 199.39,37.465 r270 top
R78 "50K" RESC2012X60N 201.93,37.465 r270 top
R79 "50K" RESC2012X60N 184.15,52.705 r90 top
R80 "50K" RESC2012X60N 186.69,52.705 r90 top
R81 "50K" RESC2012X60N 189.23,52.705 r90 top
R82 "50K" RESC2012X60N 191.77,52.705 r90 top
R83 "50K" RESC2012X60N 194.31,52.705 r90 top
R84 "50K" RESC2012X60N 196.85,52.705 r90 top
R85 "50K" RESC2012X60N 199.39,52.705 r90 top
R86 "50K" RESC2012X60N 201.93,52.705 r90 top
R87 "0R" RESC2012X60N 217.424,84.074 r90 bottom
R88 "0R" RESC2012X60N 217.424,87.376 r90 bottom
R90 "50K" RESC2012X60N 204.47,37.465 r90 top
R91 "50K" RESC2012X60N 207.01,37.465 r90 top
R92 "50K" RESC2012X60N 209.55,37.465 r90 top
R93 "50K" RESC2012X60N 212.09,37.465 r90 top
R94 "50K" RESC2012X60N 214.63,37.465 r90 top
R95 "50K" RESC2012X60N 217.17,37.465 r90 top
R96 "50K" RESC2012X60N 219.71,37.465 r90 top
R97 "50K" RESC2012X60N 222.25,37.465 r90 top
R98 "50K" RESC2012X60N 204.47,52.705 r270 top
R99 "50K" RESC2012X60N 207.01,52.705 r270 top
R100 "50K" RESC2012X60N 209.55,52.705 r270 top
R101 "50K" RESC2012X60N 212.09,52.705 r270 top
R102 "50K" RESC2012X60N 214.63,52.705 r270 top
R103 "50K" RESC2012X60N 217.17,52.705 r270 top
R104 "50K" RESC2012X60N 219.71,52.705 r270 top
R105 "50K" RESC2012X60N 222.25,52.705 r270 top
RP1 "22" RESC2012X60N 168.275,123.825 r0 top
RP2 "22" RESC2012X60N 168.275,121.285 r0 top
RP3 "22" RESC2012X60N 168.275,118.745 r0 top
RP4 "22" RESC2012X60N 168.275,116.205 r0 top
RP5 "22" RESC2012X60N 168.275,113.665 r0 top
RP6 "22" RESC2012X60N 168.275,111.125 r0 top
RP8 "22" RESC2012X60N 168.275,108.585 r0 top
RP10 "22" RESC2012X60N 168.275,106.045 r0 top
RP11 "22" RESC2012X60N 168.275,103.505 r0 top
RP12 "22" RESC2012X60N 168.275,100.965 r0 top
RP13 "22" RESC2012X60N 168.275,98.425 r0 top
RP14 "22" RESC2012X60N 168.275,95.885 r0 top
RP15 "22" RESC2012X60N 168.275,93.345 r0 top
RP16 "22" RESC2012X60N 168.275,90.805 r0 top
RP17 "22" RESC2012X60N 168.275,88.265 r0 top
RP18 "22" RESC2012X60N 168.275,85.725 r0 top
RP19 "22" RESC2012X60N 184.15,44.72 r90 top
RP20 "22" RESC2012X60N 186.69,44.72 r90 top
RP21 "22" RESC2012X60N 189.23,44.72 r90 top
RP22 "22" RESC2012X60N 191.77,44.72 r90 top
RP23 "22" RESC2012X60N 194.31,44.72 r90 top
RP24 "22" RESC2012X60N 196.85,44.72 r90 top
RP25 "22" RESC2012X60N 199.39,44.72 r90 top
RP26 "22" RESC2012X60N 201.93,44.72 r90 top
RP27 "22" RESC2012X60N 204.47,44.72 r90 top
RP28 "22" RESC2012X60N 207.01,44.72 r90 top
RP29 "22" RESC2012X60N 209.55,44.72 r90 top
RP30 "22" RESC2012X60N 212.09,44.72 r90 top
RP31 "22" RESC2012X60N 214.63,44.72 r90 top
RP32 "22" RESC2012X60N 217.17,44.72 r90 top
RP33 "22" RESC2012X60N 219.71,44.72 r90 top
RP34 "22" RESC2012X60N 222.25,44.72 r90 top
S1 "CLKIN" AMPHENOL_132134 240.03,137.16 r0 top
S2 "DATACLK" AMPHENOL_132134 196.85,137.16 r0 top
S3 "OUT1" AMPHENOL_132134 248.158,106.68 r0 top
S4 "OUT2" AMPHENOL_132134 248.158,72.39 r0 top
S5 "OPCLK" AMPHENOL_132134 198.755,64.77 r0 top
S6 "IQ" AMPHENOL_132134 167.005,48.26 r0 top
T1 "T1-1T" XFMR_COILCRAFT_Q4470#1 226.06,112.395 r270 top
T2 "T1-1T" XFMR_COILCRAFT_Q4470#2 241.3,98.425 r0 top
T3 "T1-1T" XFMR_COILCRAFT_Q4470#2 241.3,80.645 r0 top
T4 "ETC1-1-13" "XFMR_MA-COM_SM-22 (H260)" 280.035,76.835 r0 top
T5 "ADTL1-12" XFMR_COILCRAFT_PWB 271.145,94.615 r0 top
T6 "ADTL1-12" XFMR_COILCRAFT_PWB 271.145,84.455 r0 top
TP2 "RED" VERO_20-2136 180.34,133.35 r0 top
TP3 "BLK" VERO_20-2136 175.26,133.35 r0 top
TP4 "RED" VERO_20-2136 269.24,133.35 r0 top
TP5 "BLK" VERO_20-2136 264.16,133.35 r0 top
TP6 "RED" VERO_20-2136 223.52,133.35 r0 top
TP7 "BLK" VERO_20-2136 218.44,133.35 r0 top
TP8 "WHT" VERO_20-2136 226.06,77.47 r0 top
TP9 "WHT" VERO_20-2136 229.87,72.39 r0 top
TP10 "WHT" VERO_20-2136 226.06,67.31 r0 top
TP11 "WHT" VERO_20-2136 229.87,60.96 r0 top
TP14 "WHT" VERO_20-2136 189.23,125.73 r0 top
TP15 "WHT" VERO_20-2136 233.045,123.825 r0 top
U1 "1273HA044" 4235.88-1 206.375,89.535 r270 top
U2 "AD8345AREZ" SOP65P640X105-17N-S300 280.67,89.535 r90 top
U3 "SN74ACT86D" SOIC127P600X175-14N 206.375,121.285 r0 top
U4 "SN74ACT86D" SOIC127P600X175-14N 168.91,63.5 r0 top
U5 "74AC14MTC" MTC14_N 259.08,52.07 r270 top
U6 "74AC14MTC" MTC14_N 246.38,52.07 r270 top
U7 "74LCX112" 74LCX112 171.45,64.135 r270 bottom
U8 "MC100EPT22D" 751-06_N 241.935,121.92 r90 top

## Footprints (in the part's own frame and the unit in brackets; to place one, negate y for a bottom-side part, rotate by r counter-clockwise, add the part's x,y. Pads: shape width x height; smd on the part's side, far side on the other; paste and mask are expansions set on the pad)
6-0805_L [mm] "Chip Resistor, Body 2.0x1.2mm, IPC High Density"
  rect 1x1.3 smd: 1(-0.8,0) 2(0.8,0)
  silkscreen extent 0,-0.55 0,0.55, body extent -1.07,-0.7 1.07,0.7, height 0.7
12Z-2010 [mm] "Chip Resistor, Body 5.0x2.5mm, IPC High Density"
  rect 1.2x2.6 smd: 1(-2.2,0) 2(2.2,0)
  silkscreen extent -1.2,-1.2 1.2,1.2, body extent -2.58,-1.33 2.58,1.33, height 0.9
74LCX112 [mm]
  rect 2.2x0.6 smd: 1(-4.445,4.445) 2(-4.445,3.175) 3(-4.445,1.905) 4(-4.445,0.635) 5(-4.445,-0.635) 6(-4.445,-1.905) 7(-4.445,-3.175) 8(-4.445,-4.445) 9(3.175,-4.445) 10(3.175,-3.175) 11(3.175,-1.905) 12(3.175,-0.635) 13(3.175,0.635) 14(3.175,1.905) 15(3.175,3.175) 16(3.175,4.445)
  silkscreen extent -3.25,-5 2,5
751-06_N [mm] "SOIC, 8-Leads, Body 4.9x3.9mm, Pitch 1.27mm, IPC Medium Density"
  oval 2.2x0.6 smd: 1(-2.4,1.905) 2(-2.4,0.635) 3(-2.4,-0.635) 4(-2.4,-1.905) 5(2.4,-1.905) 6(2.4,-0.635) 7(2.4,0.635) 8(2.4,1.905)
  silkscreen extent -2.52,-2.5 0.9,2.88, body extent -1.95,-2.45 1.95,2.45, height 1.75
4235.88-1 [mm]
  rect 7x0.37 smd: 1(-13.75,6.875) 2(-13.75,6.25) 3(-13.75,5.625) 4(-13.75,5) 5(-13.75,4.375) 6(-13.75,3.75) 7(-13.75,3.125) 8(-13.75,2.5) 9(-13.75,1.875) 10(-13.75,1.25) 11(-13.75,0.625) 12(-13.75,0) 13(-13.75,-0.625) 14(-13.75,-1.25) 15(-13.75,-1.875) 16(-13.75,-2.5) 17(-13.75,-3.125) 18(-13.75,-3.75) 19(-13.75,-4.375) 20(-13.75,-5) 21(-13.75,-5.625) 22(-13.75,-6.25) 45(14.375,-6.25) 46(14.375,-5.625) 47(14.375,-5) 48(14.375,-4.375) 49(14.375,-3.75) 50(14.375,-3.125) 51(14.375,-2.5) 52(14.375,-1.875) 53(14.375,-1.25) 54(14.375,-0.625) 55(14.375,0) 56(14.375,0.625) 57(14.375,1.25) 58(14.375,1.875) 59(14.375,2.5) 60(14.375,3.125) 61(14.375,3.75) 62(14.375,4.375) 63(14.375,5) 64(14.375,5.625) 65(14.375,6.25) 66(14.375,6.875)
  rect 0.37x7 smd: 23(-6.25,-13.75) 24(-5.625,-13.75) 25(-5,-13.75) 26(-4.375,-13.75) 27(-3.75,-13.75) 28(-3.125,-13.75) 29(-2.5,-13.75) 30(-1.875,-13.75) 31(-1.25,-13.75) 32(-0.625,-13.75) 33(0,-13.75) 34(0.625,-13.75) 35(1.25,-13.75) 36(1.875,-13.75) 37(2.5,-13.75) 38(3.125,-13.75) 39(3.75,-13.75) 40(4.375,-13.75) 41(5,-13.75) 42(5.625,-13.75) 43(6.25,-13.75) 44(6.875,-13.75) 67(6.875,14.375) 68(6.25,14.375) 69(5.625,14.375) 70(5,14.375) 71(4.375,14.375) 72(3.75,14.375) 73(3.125,14.375) 74(2.5,14.375) 75(1.875,14.375) 76(1.25,14.375) 77(0.625,14.375) 78(0,14.375) 79(-0.625,14.375) 80(-1.25,14.375) 81(-1.875,14.375) 82(-2.5,14.375) 83(-3.125,14.375) 84(-3.75,14.375) 85(-4.375,14.375) 86(-5,14.375) 87(-5.625,14.375) 88(-6.25,14.375)
  silkscreen extent -9.5,-9.5 10,10
AMPHENOL_132134 [mm] "50 Ohm Through Hole SMA Straight PCB Jack"
  round 2.2 hole 1.5: 1(0,0)
  round 2.4 hole 1.7: 2(-2.54,2.54) 2(-2.54,-2.54) 2(2.54,2.54) 2(2.54,-2.54)
  silkscreen extent -3.5,-3.5 3.5,3.5, body extent -3.5,-3.5 3.5,3.5, height 9.53
CAPC2012X135N [mm] "Chip Capacitor, Body 2.0x1.25mm, IPC Medium Density"
  rect 1.05x1.4 smd: 1(-0.9,0) 2(0.9,0)
  silkscreen extent 0,-0.58 0,0.58, body extent -1.05,-0.67 1.05,0.68, height 1.25
CAPMP3528X210N [mm] "Capacitor, Polarized, Molded  Body 3.5x2.8mm, IPC Medium Density"
  rect 1.8x2.25 smd: 1(-1.45,0) 2(1.45,0)
  silkscreen extent -2.52,-1.5 1.85,1.73, body extent -1.85,-1.5 1.85,1.5, height 2.1
MTC14_N [mm] "TSOP, 14-Leads, Body 5x4.4mm, Pitch 0.65mm, IPC Medium Density"
  oval 1.7x0.35 smd: 1(-2.85,1.95) 2(-2.85,1.3) 3(-2.85,0.65) 4(-2.85,0) 5(-2.85,-0.65) 6(-2.85,-1.3) 7(-2.85,-1.95) 8(2.85,-1.95) 9(2.85,-1.3) 10(2.85,-0.65) 11(2.85,0) 12(2.85,0.65) 13(2.85,1.3) 14(2.85,1.95)
  silkscreen extent -2.97,-2.55 1.6,2.8, body extent -2.25,-2.55 2.25,2.55, height 1.1
PLS2 [mm] "footprint PLS2"
  round 1.5 hole 0.9: 1(0,0) 2(0,2.54)
  silkscreen extent -1.25,-1.25 1.25,3.75
RESC0603X28N [mm] "Chip Resistor, EIA 0201, Metric 0603, Body 0.6 x 0.3mm, IPC Medium Density"
  rect 0.46x0.42 smd: 1(-0.33,0) 2(0.33,0)
  body extent -0.32,-0.17 0.33,0.18, height 0.28
RESC2012X60N [mm] "Chip Resistor, EIA 0805, Metric 2012, Body 2.0x1.2mm, IPC Medium Density"
  rect 0.95x1.4 smd: 1(-1,0) 2(1,0)
  silkscreen extent 0,-0.55 0,0.55, body extent -1.1,-0.67 1.1,0.68, height 0.6
RESC2013X64N [mm] "Chip Resistor, EIA 0805, Metric 2013, Body 2.03x1.27mm, IPC Medium Density"
  rect 0.95x1.45 smd: 1(-1,0) 2(1,0)
  silkscreen extent 0,-0.55 0,0.55, body extent -1.02,-0.63 1.02,0.64, height 0.64
"SKS-HIRSCHMANN_930 176-100" [mm] "Black Socket For Banana 4mm"
  round 10.5 hole 6.2: 1(0,0)
  silkscreen extent -5.5,-5.5 5.5,5.5, body extent -5,-5 5,5, height 9.3
"SKS-HIRSCHMANN_930 176-101" [mm] "Red Socket For Banana 4mm"
  round 10.5 hole 6.2: 1(0,0)
  silkscreen extent -5.5,-5.5 5.5,5.5, body extent -5,-5 5,5, height 9.3
SOIC127P600X175-14N [mm] "SOIC 14, Pitch 1.27mm - Body 4x8.75mm, IPC Medium Density"
  rect 1.55x0.6 smd: 1(-2.7,3.81) 2(-2.7,2.54) 3(-2.7,1.27) 4(-2.7,0) 5(-2.7,-1.27) 6(-2.7,-2.54) 7(-2.7,-3.81) 8(2.7,-3.81) 9(2.7,-2.54) 10(2.7,-1.27) 11(2.7,0) 12(2.7,1.27) 13(2.7,2.54) 14(2.7,3.81)
  silkscreen extent -2.52,-4.4 1.55,4.78, body extent -3.1,-4.37 3.1,4.38, height 1.75
SOP65P640X105-17N-S300 [mm] "SOP, 0.65mm Pitch; 16 Pin, 4.40mm W X 5.00mm L X 1.05mm H body (w/thermal tab 3.00mm X 3.00mm), IPC Medium Density"
  rect 1.5x0.45 smd: 1(-2.95,2.275) 2(-2.95,1.625) 3(-2.95,0.975) 4(-2.95,0.325) 5(-2.95,-0.325) 6(-2.95,-0.975) 7(-2.95,-1.625) 8(-2.95,-2.275) 9(2.95,-2.275) 10(2.95,-1.625) 11(2.95,-0.975) 12(2.95,-0.325) 13(2.95,0.325) 14(2.95,0.975) 15(2.95,1.625) 16(2.95,2.275)
  rect 3x3 smd: 17(0,0)
  silkscreen extent -3.57,-2.5 1.85,3.12, body extent -3.2,-2.55 3.2,2.55, height 1.05
VERO_20-2136 [mm] "Black Bead PCB Terminal Test Pin (1.32 mm hole)"
  round 2 hole 1.3: 1(0,0)
  silkscreen extent -1.5,-1.5 1.5,1.5, body extent -1.5,-1.5 1.5,1.5, height 5.4
XFMR_COILCRAFT_PWB [mm] "Surface Mount Wideband RF Transformer, Body 6.48mm x 6.48mm"
  rect 2.54x1.65 smd: 1(-2.425,2.54) 2(-2.425,0) 3(-2.425,-2.54) 4(2.425,-2.54) 5(2.425,0) 6(2.425,2.54)
  silkscreen extent -4.52,-3.49 1.77,3.49, body extent -3.6,-3.48 3.6,3.49, height 4.65
XFMR_COILCRAFT_Q4470#1 [mm] "Miniature Surface Mount Transformer, Body 6.6mm x 8.89mm"
  rect 1.27x1.27 hole 0.72 unplated: 1(-4.13,2.54)
  round 1.27 hole 0.72 unplated: 2(-4.13,0) 3(-4.13,-2.54) 4(4.13,-2.54) 5(4.13,0) 6(4.13,2.54)
  silkscreen extent -4.25,-3.53 3.15,3.93, body extent -4.44,-3.49 4.45,3.5, height 5.46
XFMR_COILCRAFT_Q4470#2 [mm] "Miniature Surface Mount Transformer, Body 6.6mm x 8.89mm"
  rect 1.27x1.27 hole 0.72 unplated: 1(-4.13,-2.54)
  round 1.27 hole 0.72 unplated: 2(-4.13,0) 3(-4.13,2.54) 4(4.13,2.54) 5(4.13,0) 6(4.13,-2.54)
  silkscreen extent -4.25,-3.92 3.15,3.53, body extent -4.44,-3.5 4.45,3.49, height 5.46
"XFMR_MA-COM_SM-22 (H260)" [mm] "MA-COM E-Serie RF 1:1 Transmission Line Ttransformer 4.5-3000MHz"
  rect 0.76x1.4 smd: 1(-1.27,1.715) 2(0,1.715) 3(1.27,1.715) 4(1.27,-1.715) 5(-1.27,-1.715)
  silkscreen extent -2.3,-1.3 1.91,1.72, body extent -1.9,-1.9 1.91,1.91, height 2.6

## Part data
C1 C2 C3 C4 C5 C6 C7 C8 C9 C10 C28 C30 C30 C31 C43 C44 C49 C52 C62 C63 C64 C65 C66 C72: library part CTE3528-21_2.2UF_25V_10%, "Polarised capacitor"
C11 C12 C13 C14 C15 C16 C17 C18 C19 C20 C21 C22 C23 C24 C25 C26 C27 C29 C32 C33 C34 C35 C36 C37 C38 C39 C40 C41 C42 C45 C46 C47 C48 C50 C51 C53 C54 C55 C56 C57 C58 C59 C60 C67 C68 C69 C70 C71 C73 C74 C75 C76 C77 C78 C79 C80 C81: library part CC0805_NO-VALUE, "Non-polarised capacitor"
J3 J4 J8: library part "SKS-HIRSCHMANN_930 176-101", "Single Terminal Socket"
J5 J6 J7: library part "SKS-HIRSCHMANN_930 176-100", "Single Terminal Socket"
J9 J10 S1 S2 S3 S4 S5 S6: library part AMPHENOL_132134
JP7 JP21 JP44 JP45: library part R0201_0R_JUMPER, "Resistor"
JP18 JP19 JP20 JP23 JP42: "Jumper Wire"
L1 L2 L3 L4 L5 L6 L7 L8: library part Ind, "Inductor"
R1 R2 R3 R4 R5 R6 R9 R10 R11 R12 R13 R13 R14 R14 R15 R16 R17 R18 R18 R19 R20 R21 R22 R23 R24 R25 R26 R27 R28 R29 R30 R31 R32 R33 R34 R35 R36 R37 R38 R39 R40 R41 R42 R43 R44 R45 R46 R47 R48 R49 R50 R51 R52 R53 R54 R55 R56 R57 R58 R59 R60 R61 R62 R63 R64 R65 R66 R67 R68 R69 R70 R71 R72 R73 R74 R75 R76 R77 R78 R79 R80 R81 R82 R83 R84 R85 R86 R87 R88 R90 R91 R92 R93 R94 R95 R96 R97 R98 R99 R100 R101 R102 R103 R104 R105 RP1 RP2 RP3 RP4 RP5 RP6 RP8 RP10 RP11 RP12 RP13 RP14 RP15 RP16 RP17 RP18 RP19 RP20 RP21 RP22 RP23 RP24 RP25 RP26 RP27 RP28 RP29 RP30 RP31 RP32 RP33 RP34: library part R0805_NO-VALUE, "Resistor"
R7 R8: library part R0805_10K_0.01%_0.2W_0.2PPM_VISHAY_VSMP, "Resistor - 0.01%"
T1 T2 T3: library part XFMR_COILCRAFT_Q4470-CLD, "Miniature SMT Transformer"
T4: library part XFMR_MA-COM_MABA-007159-000000, "MA-COM E-Serie RF 1:1 Transmission Line Ttransformer 4.5-3000MHz"
T5 T6: library part XFMR_COILCRAFT_PWB-1-BLC, "SMT Transformer PWB Serie Type B Pinout"
TP2 TP3 TP4 TP5 TP6 TP7 TP8 TP9 TP10 TP11 TP14 TP15: library part VERO_20-2136, "Test Point"
U2: "140MHz to 1000MHz Quadrature Modulator"
U3 U4: "Quadruple 2-Input Exclusive-OR Gates"
U5 U6: "Hex Schmitt-Trigger Inverter, 14-Pin TSOP"
U8: "Dual LVTTL/LVCMOS to Differential LVPECL Translator"

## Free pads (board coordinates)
  round 4 hole 3.5: 0(154.305,29.845) 0(294.005,29.845) 0(294.005,155.575)
  round 4.2 hole 3.5: 0(154.305,155.575)
  round 1.524 hole 0.9: 0(278.765,122.555) 0(280.67,122.555) 0(282.575,122.555) 0(284.48,122.555) 0(286.385,122.555) 0(288.29,122.555) 0(290.195,122.555) 0(292.1,122.555) 0(294.005,122.555) 0(295.91,122.555) 1(278.765,124.46) 1(280.67,124.46) 1(282.575,124.46) 1(284.48,124.46) 1(286.385,124.46) 1(288.29,124.46) 1(290.195,124.46) 1(292.1,124.46) 1(294.005,124.46) 1(295.91,124.46) 2(278.765,126.365) 2(280.67,126.365) 2(282.575,126.365) 2(284.48,126.365) 2(286.385,126.365) 2(288.29,126.365) 2(290.195,126.365) 2(292.1,126.365) 2(294.005,126.365) 2(295.91,126.365) 3(278.765,128.27) 3(280.67,128.27) 3(282.575,128.27) 3(284.48,128.27) 3(286.385,128.27) 3(288.29,128.27) 3(290.195,128.27) 3(292.1,128.27) 3(294.005,128.27) 3(295.91,128.27) 4(278.765,130.175) 4(280.67,130.175) 4(282.575,130.175) 4(284.48,130.175) 4(286.385,130.175) 4(288.29,130.175) 4(290.195,130.175) 4(292.1,130.175) 4(294.005,130.175) 4(295.91,130.175) 5(284.48,132.08) 5(286.385,132.08) 5(288.29,132.08) 5(290.195,132.08) 5(292.1,132.08) 5(294.005,132.08) 5(295.91,132.08) 6(284.48,133.985) 6(286.385,133.985) 6(288.29,133.985) 6(290.195,133.985) 6(292.1,133.985) 6(294.005,133.985) 6(295.91,133.985) 7(284.48,135.89) 7(286.385,135.89) 7(288.29,135.89) 7(290.195,135.89) 7(292.1,135.89) 7(294.005,135.89) 7(295.91,135.89)

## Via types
v1: diameter 0.95, hole 0.4, Top Layer to Bottom Layer, 112 vias
v2: diameter 0.95, hole 0.4, Top Layer to Bottom Layer, tented bottom, 1 vias

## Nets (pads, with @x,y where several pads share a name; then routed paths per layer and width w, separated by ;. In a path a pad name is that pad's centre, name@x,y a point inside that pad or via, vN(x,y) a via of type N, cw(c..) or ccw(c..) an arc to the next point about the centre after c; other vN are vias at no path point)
AD0: R70.1 RP18.2 U1.32 | length 27.4
  Top Layer w0.254: RP18.2@169.275,85.725 170.053,85.725 171.323,84.455 177.165,84.455 177.546,84.836 177.546,85.725 178.435,85.725 182.88,90.17 U1.32@193.26,90.17
AD1: R69.1 RP17.2 U1.31 | length 26.6
  Top Layer w0.254: RP17.2@169.275,88.265 170.053,88.265 171.323,86.995 177.165,86.995 177.546,87.376 177.546,88.265 178.435,88.265 180.95,90.78 U1.31@193.26,90.78
AD2: R68.1 RP16.2 U1.30 | length 25.8
  Top Layer w0.254: RP16.2@169.275,90.805 170.053,90.805 171.323,89.535 177.165,89.535 177.546,89.916 177.546,90.805 178.435,90.805 179.045,91.415 U1.30@193.26,91.415
AD3: R67.1 RP15.2 U1.29 | length 26
  Top Layer w0.254: RP15.2@169.275,93.345 170.053,93.345 171.323,92.075 177.165,92.075 177.546,92.456 R67.1@177.546,93.218 ; R67.1@177.546,93.345 178.435,93.345 179.756,92.024 U1.29@193.26,92.024
AD4: R66.1 RP14.2 U1.26 | length 25.9
  Top Layer w0.254: RP14.2@169.275,95.885 170.053,95.885 171.323,94.615 177.165,94.615 177.546,94.996 177.546,95.885 178.333,95.885 180.289,93.929 U1.26@192.837,93.929
AD5: R65.1 RP13.2 U1.25 | length 26.7
  Top Layer w0.254: RP13.2@169.275,98.425 170.053,98.425 171.323,97.155 177.165,97.155 177.546,97.536 177.546,98.425 178.435,98.425 182.321,94.539 U1.25@192.786,94.539
AD6: R64.1 RP12.2 U1.24 | length 27.3
  Top Layer w0.254: RP12.2@169.275,100.965 170.053,100.965 171.323,99.695 177.165,99.695 177.546,100.076 R64.1@177.546,100.838 ; R64.1@177.546,100.965 178.435,100.965 184.226,95.174 U1.24@192.684,95.174
AD7: R63.1 RP11.2 U1.23 | length 28.5
  Top Layer w0.254: RP11.2@169.275,103.505 170.053,103.505 171.323,102.235 177.165,102.235 177.546,102.616 177.546,103.505 178.435,103.505 186.157,95.783 U1.23@192.989,95.783
AD8: R54.2 RP10.2 U1.22 | length 37.3
  Top Layer w0.254: RP10.2@169.275,106.045 170.053,106.045 171.323,104.775 177.165,104.775 177.546,105.156 177.546,106.045 178.435,106.045 180.467,108.077 198.882,108.077 200.125,106.834 U1.22@200.125,103.285
AD9: R53.2 RP8.2 U1.21 | length 34.7
  Top Layer w0.254: RP8.2@169.275,108.585 170.053,108.585 171.323,107.315 177.165,107.315 177.546,107.696 R53.2@177.546,108.458 ; R53.2@177.546,108.585 199.009,108.585 200.75,106.844 U1.21@200.75,105.825
AD10: R52.2 RP6.2 U1.18 | length 40.3
  Top Layer w0.254: RP6.2@169.275,111.125 170.053,111.125 171.323,109.855 177.165,109.855 177.546,110.236 177.546,111.125 178.435,111.125 180.467,109.093 200.406,109.093 202.616,106.883 202.616,103.336 U1.18@202.565,103.285
AD11: R51.2 RP5.2 U1.17 | length 42
  Top Layer w0.254: RP5.2@169.275,113.665 170.053,113.665 171.323,112.395 177.165,112.395 177.546,112.776 177.546,113.665 178.435,113.665 182.499,109.601 200.533,109.601 203.251,106.883 U1.17@203.25,103.285
AD12: R49.2 RP4.2 U1.16 | length 43.6
  Top Layer w0.254: RP4.2@169.275,116.205 170.053,116.205 171.323,114.935 177.165,114.935 177.546,115.316 177.546,116.205 178.435,116.205 184.531,110.109 200.66,110.109 203.86,106.909 U1.16@203.86,103.285
AD13: R47.2 RP3.2 U1.15 | length 45.3
  Top Layer w0.254: RP3.2@169.275,118.745 170.053,118.745 171.323,117.475 177.165,117.475 177.546,117.856 177.546,118.745 178.435,118.745 186.563,110.617 200.787,110.617 204.495,106.909 U1.15@204.495,103.285
AD14: R46.2 RP2.2 U1.14 | length 47
  Top Layer w0.254: RP2.2@169.275,121.285 170.053,121.285 171.323,120.015 177.165,120.015 177.546,120.396 177.546,121.285 178.435,121.285 188.595,111.125 200.914,111.125 205.13,106.909 U1.14@205.13,103.285
AD15: R44.2 RP1.2 U1.13 | length 48.7
  Top Layer w0.254: RP1.2@169.275,123.825 170.053,123.825 171.323,122.555 177.165,122.555 177.546,122.936 177.546,123.825 178.308,123.825 190.5,111.633 201.041,111.633 205.74,106.934 U1.13@205.74,103.285
AGND: C2.2 C3.2 C4.2 C14.2 C15.2 C16.2 C17.2 C18.2 C19.2 C20.2 C30.2@277.04,139.7 C56.1 C57.1 C58.1 C59.1 C64.2 C68.2 C70.2 C71.2 C79.2 C80.1 J6.1 JP7.1 JP21.1 JP45.1 pad.0@295.91,122.555 pad.1@295.91,124.46 pad.2@295.91,126.365 pad.3@295.91,128.27 pad.4@295.91,130.175 pad.5@295.91,132.08 pad.6@295.91,133.985 pad.7@295.91,135.89 R7.1 R8.1 R16.1 R17.1 R34.2 R37.2 R42.2 R43.2 R88.2 S3.2 S4.2 T2.2 T2.6 T3.2 T3.6 TP5.1 U1.64 U1.69 U1.71 U1.74 U1.75 U1.78 U1.81 U1.82 U1.84 U1.85 U1.87 | length 95.2
  Top Layer w0.4: U1.64@212,75.16 212,78.752 212.496,79.248 ; 216.484,84.582 217.062,85.16 U1.71@220.75,85.16 ; 216.586,84.277 216.94,83.923 ; 216.902,83.91 U1.69@220.75,83.91 ; v1@226.695,87.376 v1(226.822,87.249) 227.33,86.741 C18.2@227.33,85.99
  Top Layer w1: 271.526,149.86 J6.1@278.13,149.86 ; 278.13,143.002 J6.1@278.13,149.86 ; 278.13,157.226 J6.1@278.13,149.86 ; 284.988,149.86 J6.1@278.13,149.86
  Ground w1: 271.526,149.86 J6.1@278.13,149.86 ; 278.13,143.51 J6.1@278.13,149.86 ; 278.13,156.337 J6.1@278.13,149.86 ; 284.988,149.86 J6.1@278.13,149.86
  Bottom Layer w1: 271.399,149.86 J6.1@278.13,149.86 ; 278.13,143.51 J6.1@278.13,149.86 ; 278.13,156.337 J6.1@278.13,149.86 ; 284.988,149.86 J6.1@278.13,149.86
AVDD: C2.1 C3.1 C14.1 C15.1 C17.1 C18.1 C19.1 C20.1 C30.1@274.14,139.7 pad.0@278.765,122.555 pad.1@278.765,124.46 pad.2@278.765,126.365 pad.3@278.765,128.27 pad.4@278.765,130.175 R87.1 TP4.1 U1.68 U1.70 U1.73 U1.83 U1.86 U1.88 | length 61.9
  Top Layer w0.254: 271.6,139.7 271.653,139.7
  Top Layer w0.4: v1@215.673,83.285 U1.68@220.75,83.285 224.509,83.285 225.552,84.328 v1(225.552,84.836) ; U1.70@220.75,84.535 225.251,84.535 v1(225.552,84.836) ; U1.73@220.75,86.41 224.486,86.41 225.552,85.344 v1(225.552,84.836) ; U1.83@220.75,92.66 224.486,92.66 225.679,93.853 v1(225.679,93.98) ; U1.86@220.75,94.535 225.124,94.535 v1(225.679,93.98) ; U1.88@220.75,95.785 224.636,95.785 225.679,94.742 v1(225.679,93.98) ; C18.1@227.33,84.19 226.198,84.19 v1(225.552,84.836) ; C20.1@227.33,94.096 225.795,94.096 v1(225.679,93.98)
  Top Layer w0.5: v1(272.161,139.7) C30.1@274.14,139.7
  POwer w0.5: 269.24,138.684 269.24,139.7 ; 269.24,140.97 269.24,139.7 ; 270.383,139.7 269.24,139.7
  Bottom Layer w0.4: v1(215.646,83.312) 215.884,83.074 R87.1@217.424,83.074 ; C17.1@223.785,83.82 224.536,83.82 v1(225.552,84.836) ; C15.1@223.785,85.725 224.663,85.725 v1(225.552,84.836) ; C14.1@223.785,92.71 224.536,92.71 225.679,93.853 v1(225.679,93.98) ; C19.1@223.785,94.615 224.917,94.615 v1@225.615,93.916 ; v1@225.552,93.853 v1@225.615,93.916 ; C3.1@227.15,84.836 v1(225.552,84.836) ; C2.1@227.404,93.98 v1(225.679,93.98) ; v1@225.615,93.916 v1(225.679,93.98)
AVDD_IN: C64.1 J4.1 L2.2 | length 12.4
  Top Layer w1: C64.1@256.72,139.774 J4.1@256.72,149.68 ; C64.1@256.794,139.7 L2.2@259.334,139.7
BD0: R105.1 RP34.2 U1.54 | length 40.6
  Top Layer w0.254: U1.54@205.765,77.953 205.765,70.841 222.25,54.356 R105.1@222.25,53.705 222.25,53.67 223.19,53.67 223.469,53.391 223.469,47.701 222.25,46.482 RP34.2@222.25,45.72
BD1: R104.1 RP33.2 U1.52 | length 40
  Top Layer w0.254: U1.52@204.495,77.851 204.495,71.476 219.735,56.236 219.735,53.721 220.599,53.721 221.005,53.315 221.005,47.777 219.71,46.482 RP33.2@219.71,45.72
BD2: R103.1 RP32.2 U1.51 | length 36.6
  Top Layer w0.254: U1.51@203.886,75.16 203.886,71.45 217.17,58.166 R103.1@217.17,53.705 R103.1@217.17,53.645 ; R103.1@217.145,53.645 R103.1@217.17,53.645 ; RP32.2@217.17,45.72 217.17,46.482 218.465,47.777 218.465,53.315 218.135,53.645 R103.1@217.17,53.645
BD3: R102.1 RP31.2 U1.50 | length 38.5
  Top Layer w0.254: U1.50@203.251,77.851 203.251,71.45 214.655,60.046 R102.1@214.655,53.705 ; R102.1@214.605,53.67 215.57,53.67 215.925,53.315 215.925,47.777 214.63,46.482 RP31.2@214.63,45.72
BD4: R101.1 RP30.2 U1.49 | length 37.6
  Top Layer w0.254: U1.49@202.616,77.851 202.616,71.45 212.09,61.976 R101.1@212.09,53.705 R101.1@212.09,53.696 ; RP30.2@212.09,45.72 212.09,46.482 213.36,47.752 213.36,53.34 213.03,53.67 R101.1@212.141,53.67
BD5: R100.1 RP29.2 U1.48 | length 36.9
  Top Layer w0.254: U1.48@202.006,77.927 202.006,71.425 209.55,63.881 R100.1@209.55,53.705 ; RP29.2@209.55,45.72 209.55,46.482 210.795,47.727 210.795,53.365 210.515,53.645 R100.1@209.55,53.645
BD6: R99.1 RP28.2 U1.45 | length 37
  Top Layer w0.254: 200.101,70.942 206.985,64.059 ; 200.127,70.942 U1.45@200.127,77.953 ; RP28.2@207.01,45.72 207.01,46.482 208.255,47.727 208.255,53.365 207.899,53.721 R99.1@207.035,53.721 ; R99.1@207.01,53.34 R99.1@207.01,53.705 207.01,64.059
BD7: R98.1 RP27.2 U1.44 | length 52.3
  Top Layer w0.254: U1.44@192.659,82.677 189.23,82.677 188.214,81.661 188.214,74.422 192.278,70.358 192.278,61.341 196.469,57.15 201.803,57.15 204.47,54.483 R98.1@204.47,53.705 R98.1@204.47,53.696 ; R98.1@204.445,53.696 R98.1@204.47,53.696 ; RP27.2@204.47,45.72 204.47,46.482 205.715,47.727 205.715,53.365 205.384,53.696 R98.1@204.47,53.696
BD8: R86.2 RP26.2 U1.43 | length 51.5
  Top Layer w0.254: U1.43@192.532,83.312 192.481,83.261 189.052,83.261 187.706,81.915 187.706,74.168 191.77,70.104 191.77,61.087 196.215,56.642 200.304,56.642 201.905,55.042 R86.2@201.905,53.721 ; RP26.2@201.93,45.72 201.93,46.482 203.2,47.752 203.2,53.467 202.921,53.746 R86.2@201.93,53.746
BD9: R85.2 RP25.2 U1.42 | length 49.6
  Top Layer w0.254: U1.42@192.405,83.947 192.38,83.922 188.951,83.922 187.198,82.169 187.198,73.914 191.262,69.85 191.262,60.833 198.374,53.721 199.365,53.721 199.39,53.721 199.415,53.721 200.279,53.721 200.66,53.34 200.66,47.752 199.39,46.482 RP25.2@199.39,45.72
BD10: R84.2 RP24.2 U1.41 | length 49.1
  Top Layer w0.254: U1.41@192.405,84.582 192.38,84.557 188.92,84.557 186.69,82.327 186.69,73.66 190.754,69.596 190.754,60.579 196.875,54.458 R84.2@196.875,53.696 ; R84.2@196.825,53.696 R84.2@196.875,53.696 ; RP24.2@196.85,45.72 196.85,46.482 198.12,47.752 198.12,53.34 197.764,53.696 R84.2@196.875,53.696
BD11: R83.2 RP23.2 U1.40 | length 49.4
  Top Layer w0.254: U1.40@192.659,85.217 192.608,85.166 188.773,85.166 186.182,82.575 186.182,73.406 190.246,69.342 190.246,60.325 194.31,56.261 R83.2@194.31,53.705 R83.2@194.31,53.67 ; R83.2@194.285,53.67 R83.2@194.31,53.67 ; RP23.2@194.31,45.72 194.31,46.355 195.605,47.65 195.605,53.264 195.199,53.67 R83.2@194.31,53.67
BD12: R82.2 RP22.2 U1.37 | length 51.6
  Top Layer w0.254: RP22.2@191.77,45.72 191.77,46.482 193.04,47.752 193.04,53.264 192.634,53.67 R82.2@191.795,53.67 ; R82.2@191.77,53.705 191.77,58.039 189.738,60.071 189.738,69.088 184.531,74.295 184.531,83.033 188.544,87.046 U1.37@192.634,87.046
BD13: R81.2 RP21.2 U1.36 | length 51.7
  Top Layer w0.254: RP21.2@189.23,45.72 189.23,46.482 190.5,47.752 190.5,53.264 190.094,53.67 R81.2@189.23,53.67 ; R81.2@189.23,53.705 189.23,68.834 184.023,74.041 184.023,83.312 188.366,87.655 U1.36@192.634,87.655
CGND: C1.2 C11.2 C12.2 C13.1 C42.2 C49.2 C60.1 C62.2 C63.2 C69.2 J7.1 JP44.2 JP45.2 R2.1 R13.1@242.57,130.54 R14.1@241.935,114.57 R18.1@239.395,114.57 R20.2 R24.2 S1.2 T1.4 TP7.1 U1.4 U1.7 U8.5 U8.6 | length 95.2
  Top Layer w0.4: U1.7@209.5,103.285 209.5,107.238 ; 211.375,99.394 U1.4@211.375,103.285 ; C13.1@224.398,119.38 224.398,117.994 v1(224.409,117.983)
  Top Layer w1: 228.092,149.86 J7.1@234.95,149.86 ; 234.95,143.129 J7.1@234.95,149.86 ; 234.95,156.845 J7.1@234.95,149.86 ; 241.554,149.86 J7.1@234.95,149.86
  Ground w1: 228.346,149.86 234.948,149.742 J7.1@235.077,149.733 ; 234.95,142.875 J7.1@235.077,149.733 ; 234.95,156.464 235.446,149.897 J7.1@235.077,149.733 ; 241.554,149.733 J7.1@235.077,149.733
  Bottom Layer w0.254: R2.1@225.79,125.095 225.806,125.111 v1(225.806,126.619) ; R24.2@249.285,132.08 249.301,132.096 v1(249.301,133.604) ; v1(251.714,133.604) 251.73,133.588 R20.2@251.73,132.08
  Bottom Layer w1: 228.346,149.86 J7.1@234.95,149.86 ; 234.95,142.748 J7.1@234.95,149.86 ; 234.95,156.591 J7.1@234.95,149.86 ; 241.554,149.733 235.077,149.733 J7.1@234.95,149.86
CLKVDD: C1.1 C11.1 C12.1 C27.1 C42.1 C49.1 C60.2 C62.1 R3.2 R4.2 R21.2 R22.2 TP6.1 U1.1 U1.3 U8.8 | length 46.5
  Top Layer w0.4: v1@212.56,98.361 212,98.921 U1.3@212,103.285 212,107.022 213.436,108.458 C42.1@215,108.458 215,107.682 215.367,107.315 216.484,107.315 216.764,107.036 C27.1@216.764,106.07 ; v1@212.573,98.349 213.25,99.026 U1.1@213.25,103.285 ; C27.1@216.725,106.097 216.776,106.045 C27.1@216.789,106.045 ; C60.2@234.442,126.492 234.516,126.418 C49.1@237.236,126.418 ; C49.1@237.236,126.492 v1(240.03,126.492) ; U8.8@240.03,124.32 v1@240.03,126.365
  Top Layer w0.5: v1(229.108,139.7) C62.1@230.96,139.7 ; R4.2@237.49,130.429 R4.2@237.49,130.54 v1(237.49,131.699)
  POwer w0.5: 226.06,138.43 226.06,139.7 ; 226.06,140.97 226.06,139.7 ; 227.203,139.7 226.06,139.7
  Bottom Layer w0.4: C12.1@211.328,97.166 211.328,98.044 211.709,98.425 v1@212.573,98.425 ; C1.1@212.75,100.787 212.573,100.609 v1@212.573,98.425 ; C11.1@213.36,97.166 213.36,98.044 212.979,98.425 v1@212.573,98.425 ; R22.2@249.285,129.54 v1(250.571,129.54) R21.2@251.73,129.54
  Bottom Layer w0.5: R3.2@223.52,129.159 R3.2@223.52,129.27 223.536,129.286 v1(224.917,129.286)
  other v1: 212.573,98.374
CLKVDD_IN: C63.1 J3.1 L1.2 | length 12.6
  Top Layer w1: J3.1@213.54,149.68 C63.1@213.54,139.7 L1.2@216.154,139.7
